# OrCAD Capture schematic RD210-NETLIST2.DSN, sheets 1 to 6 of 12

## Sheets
1 12: size Custom
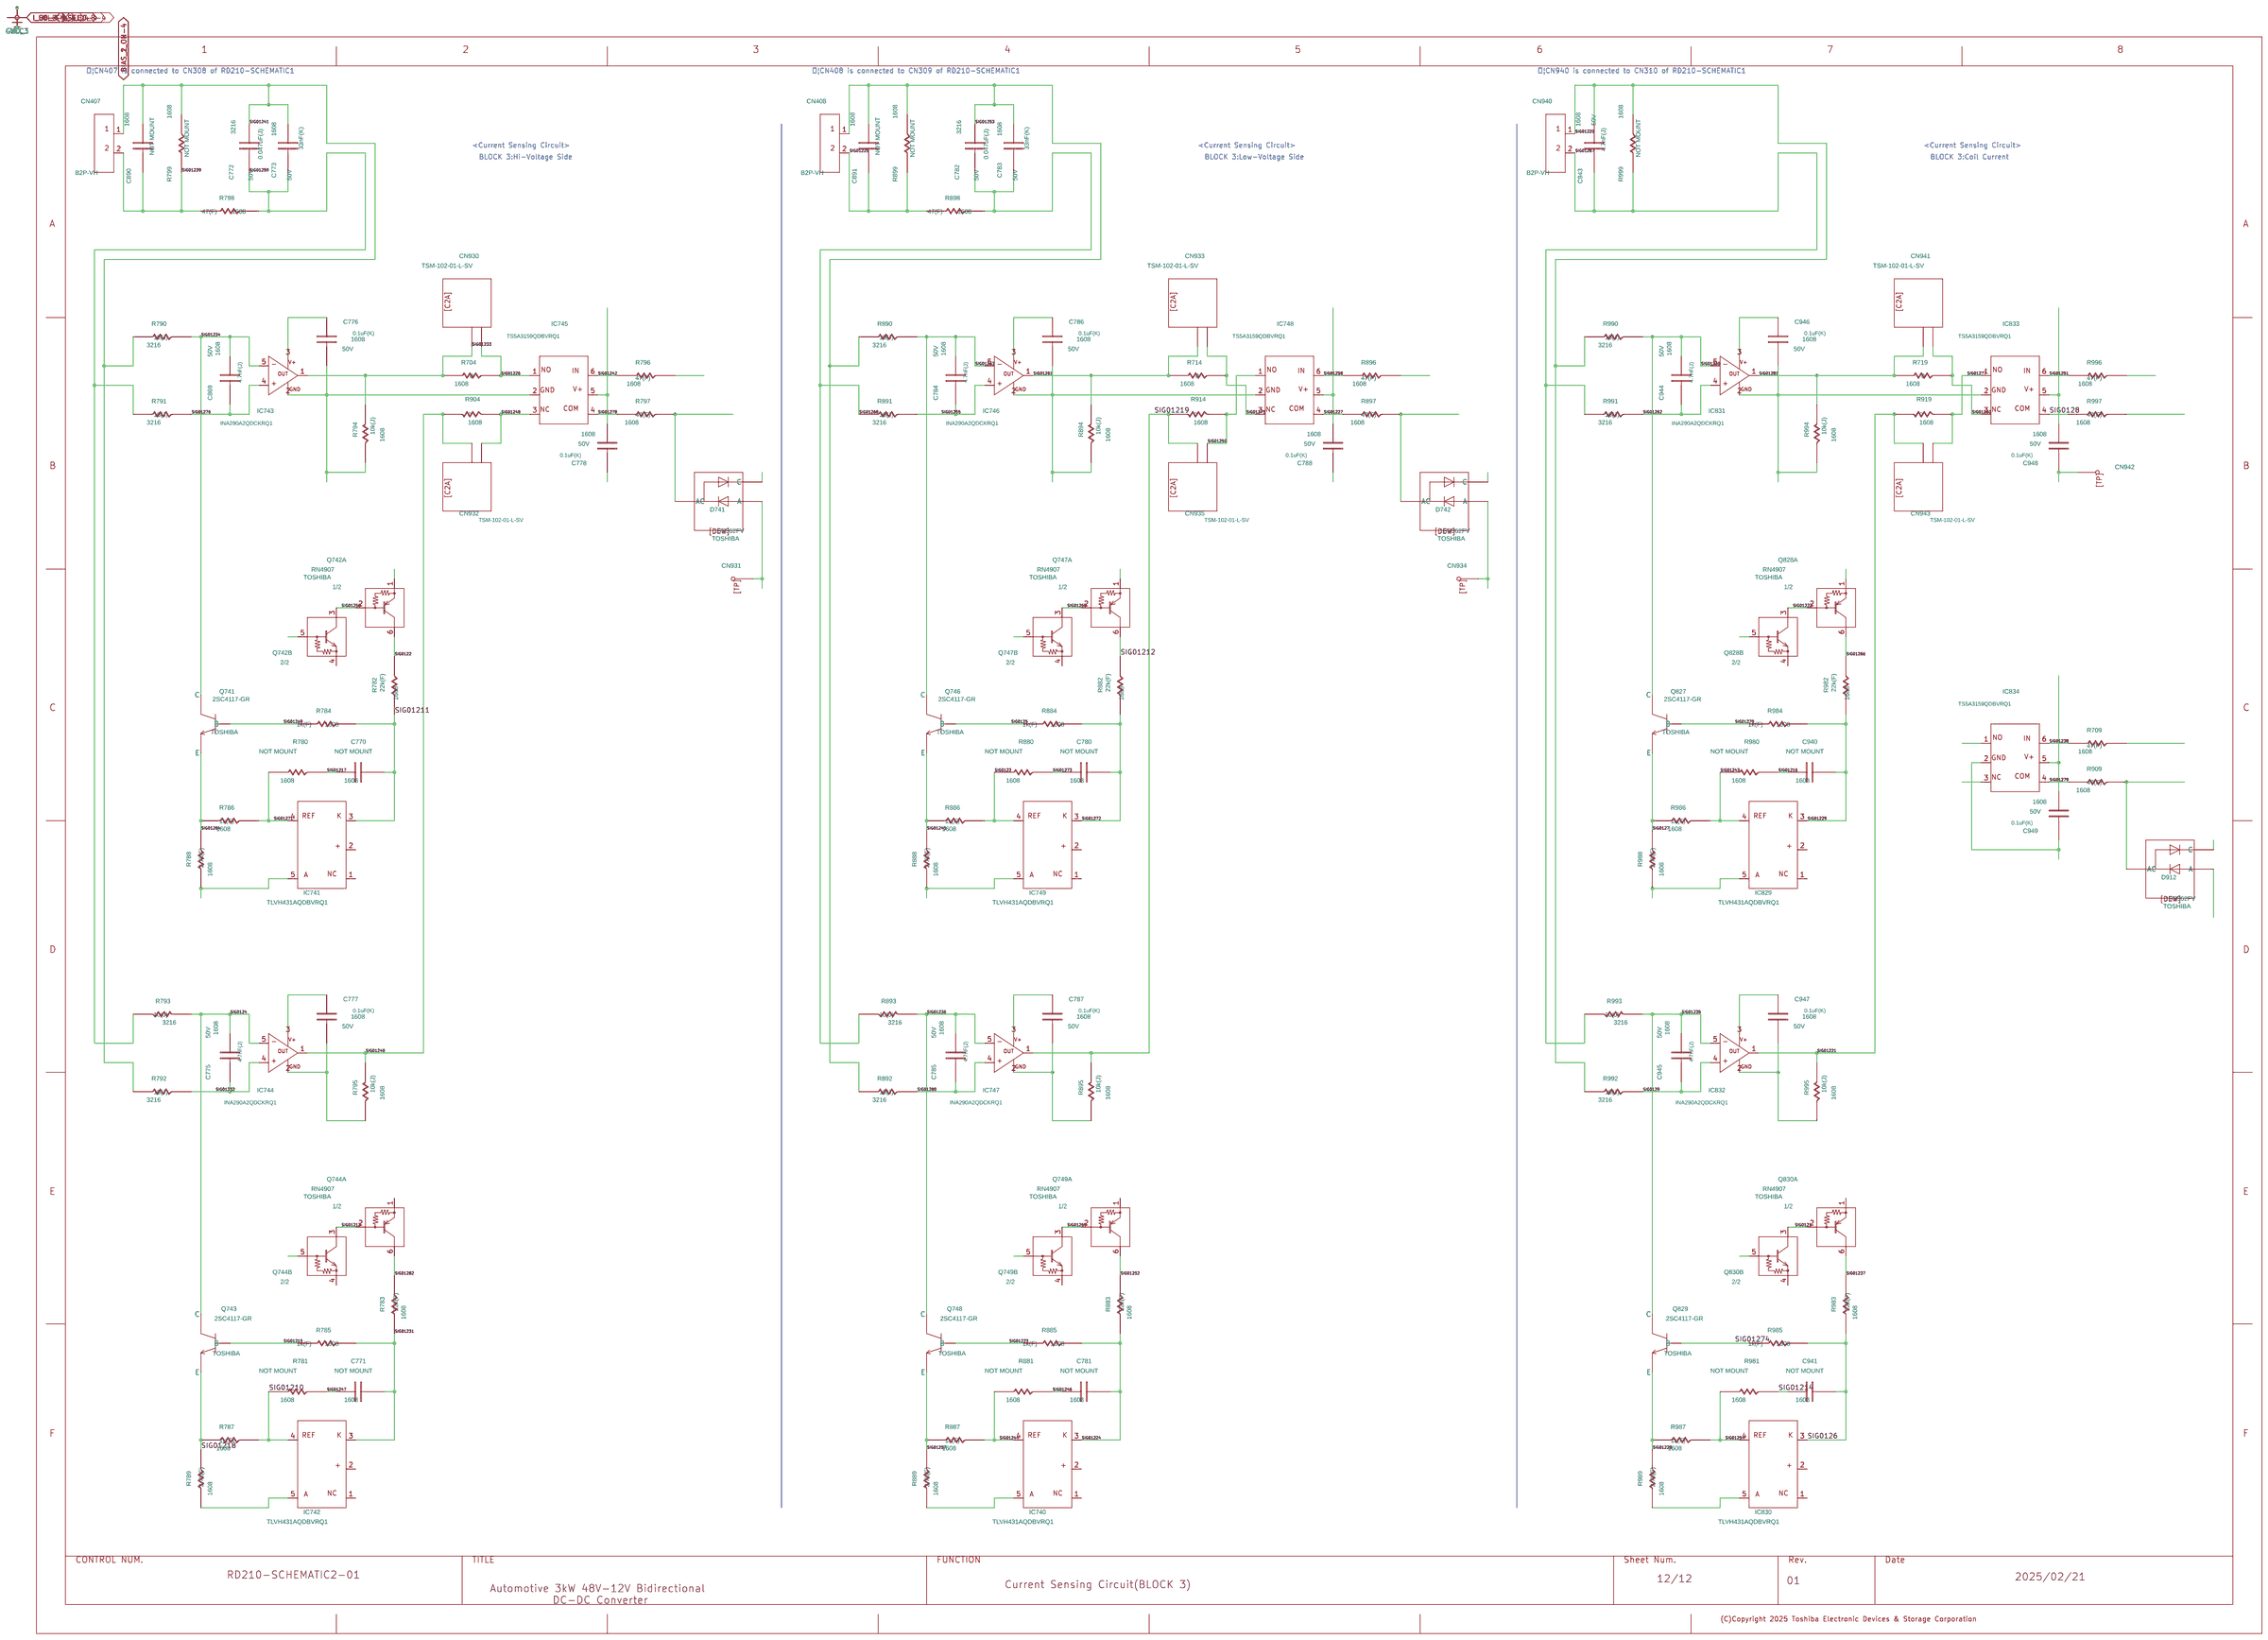
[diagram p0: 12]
2 11: size Custom
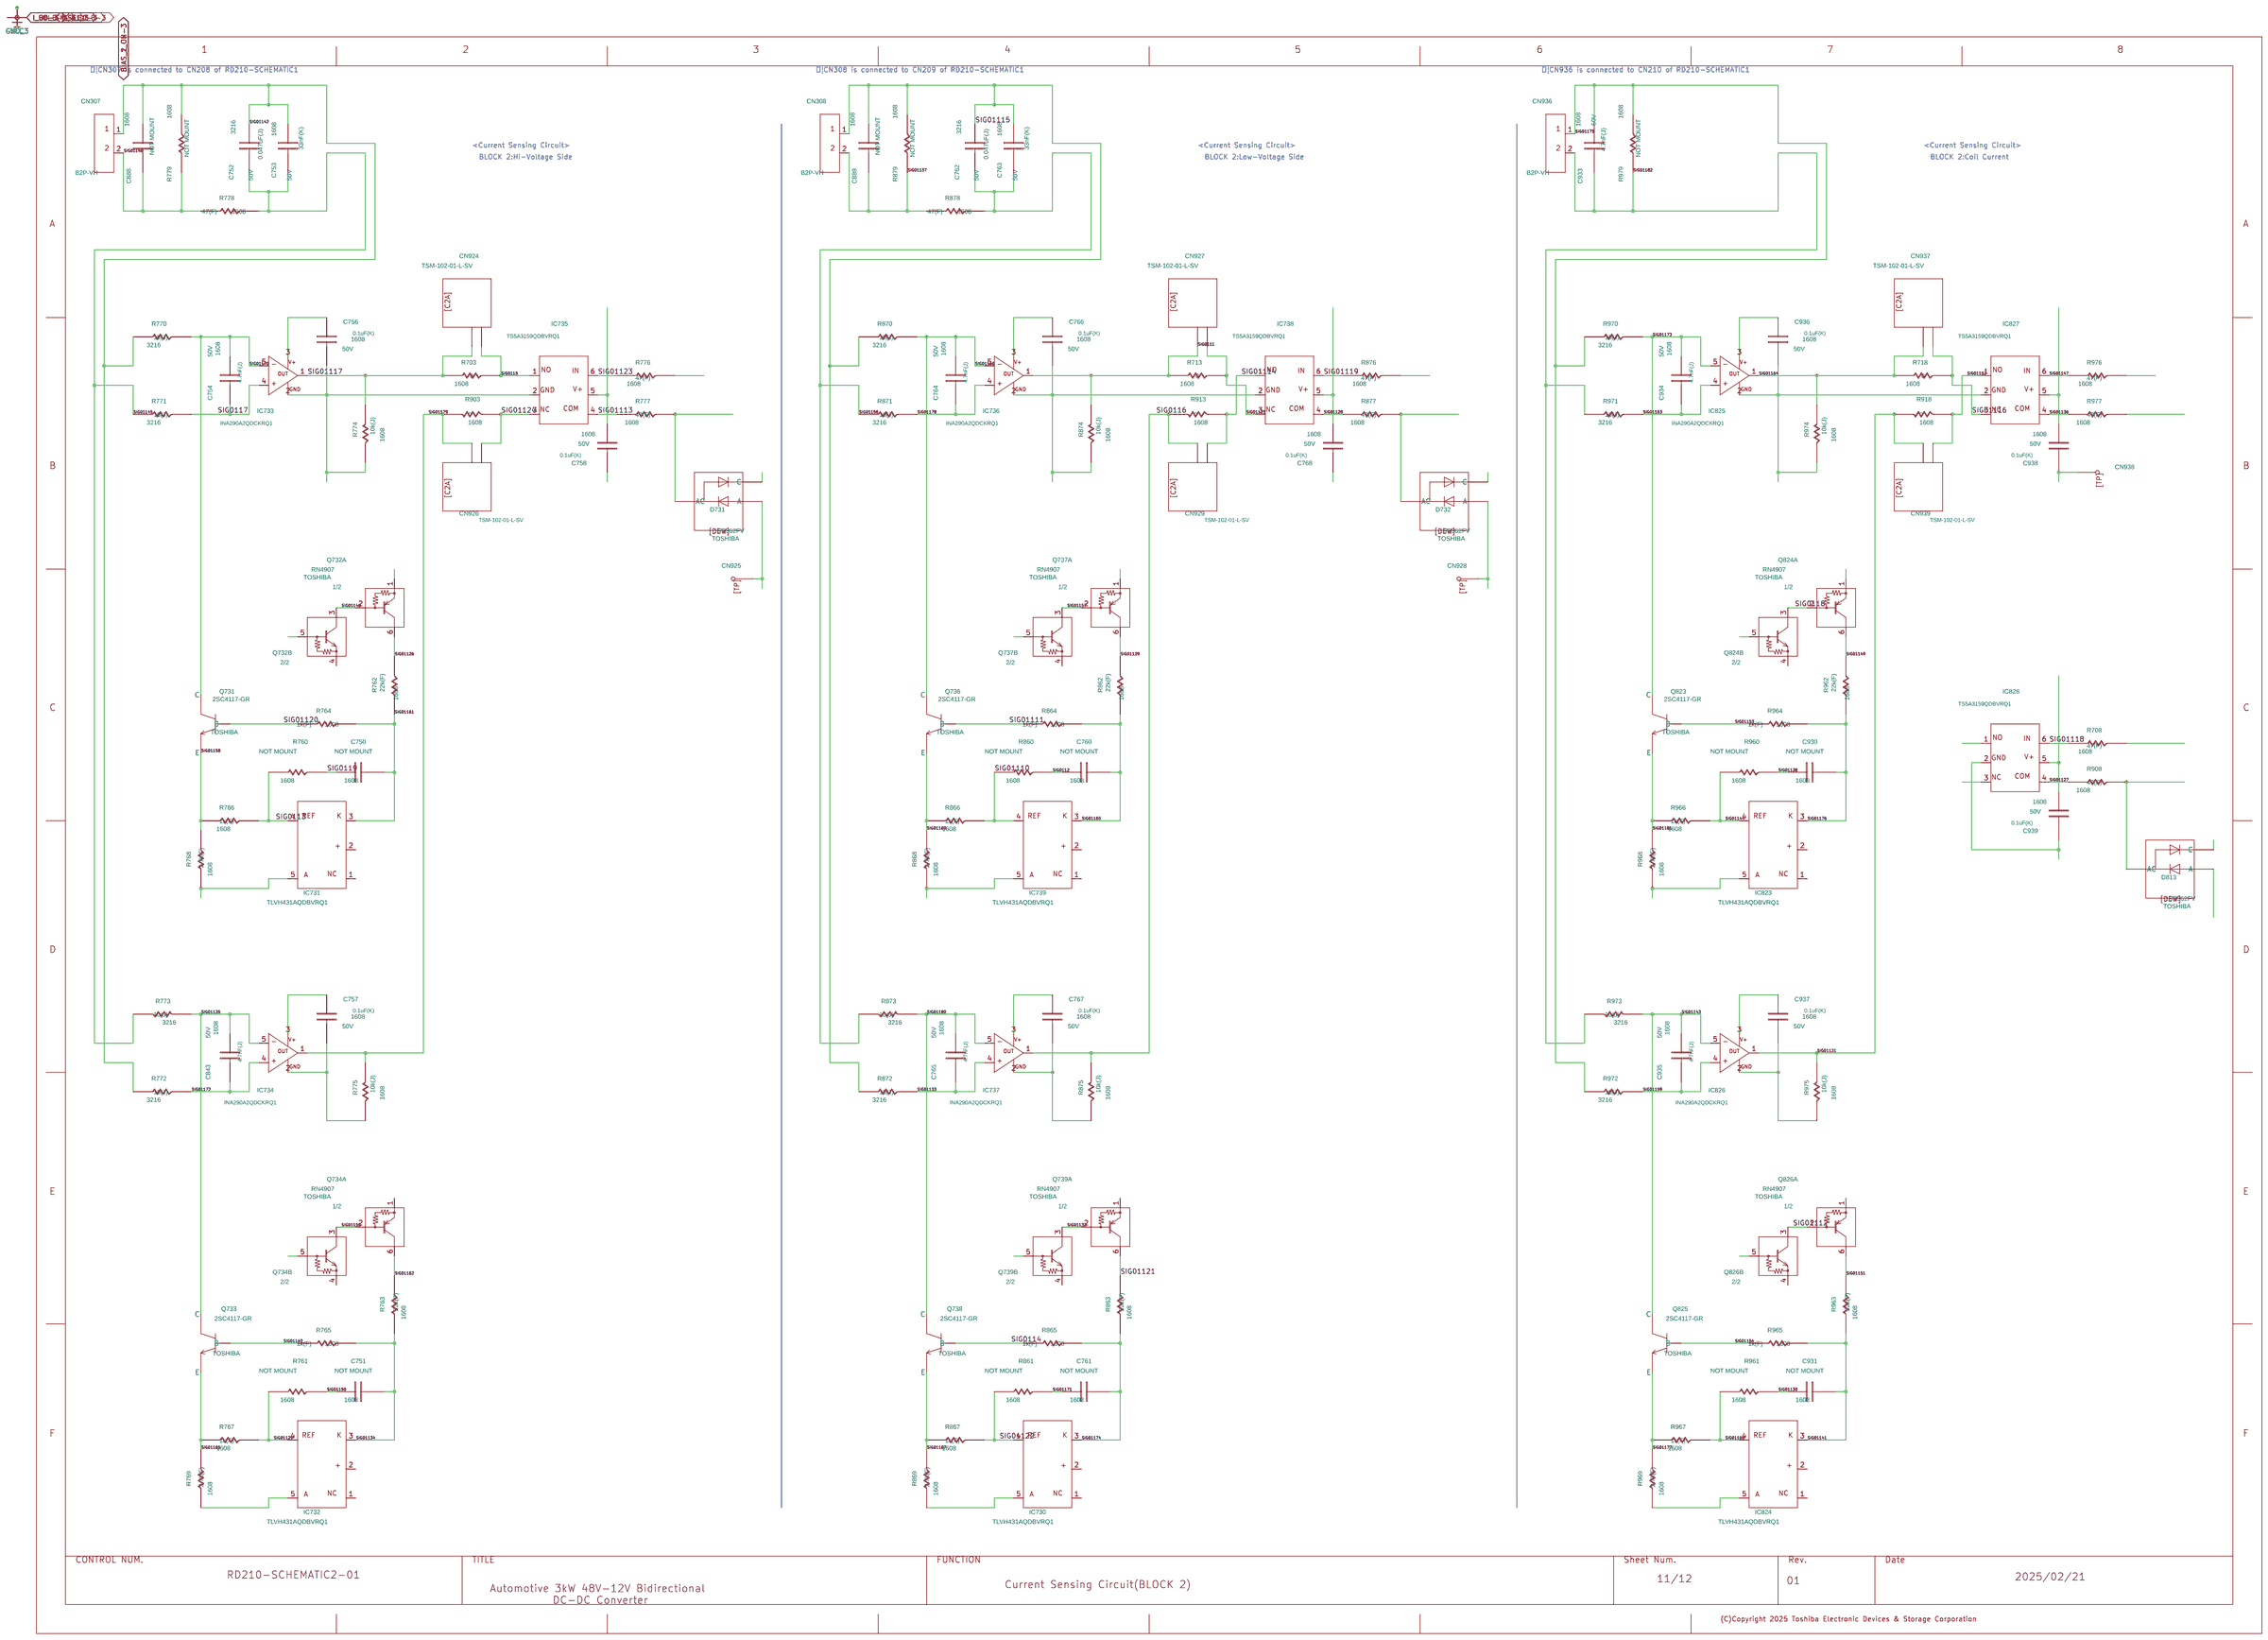
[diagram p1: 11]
3 10: size Custom
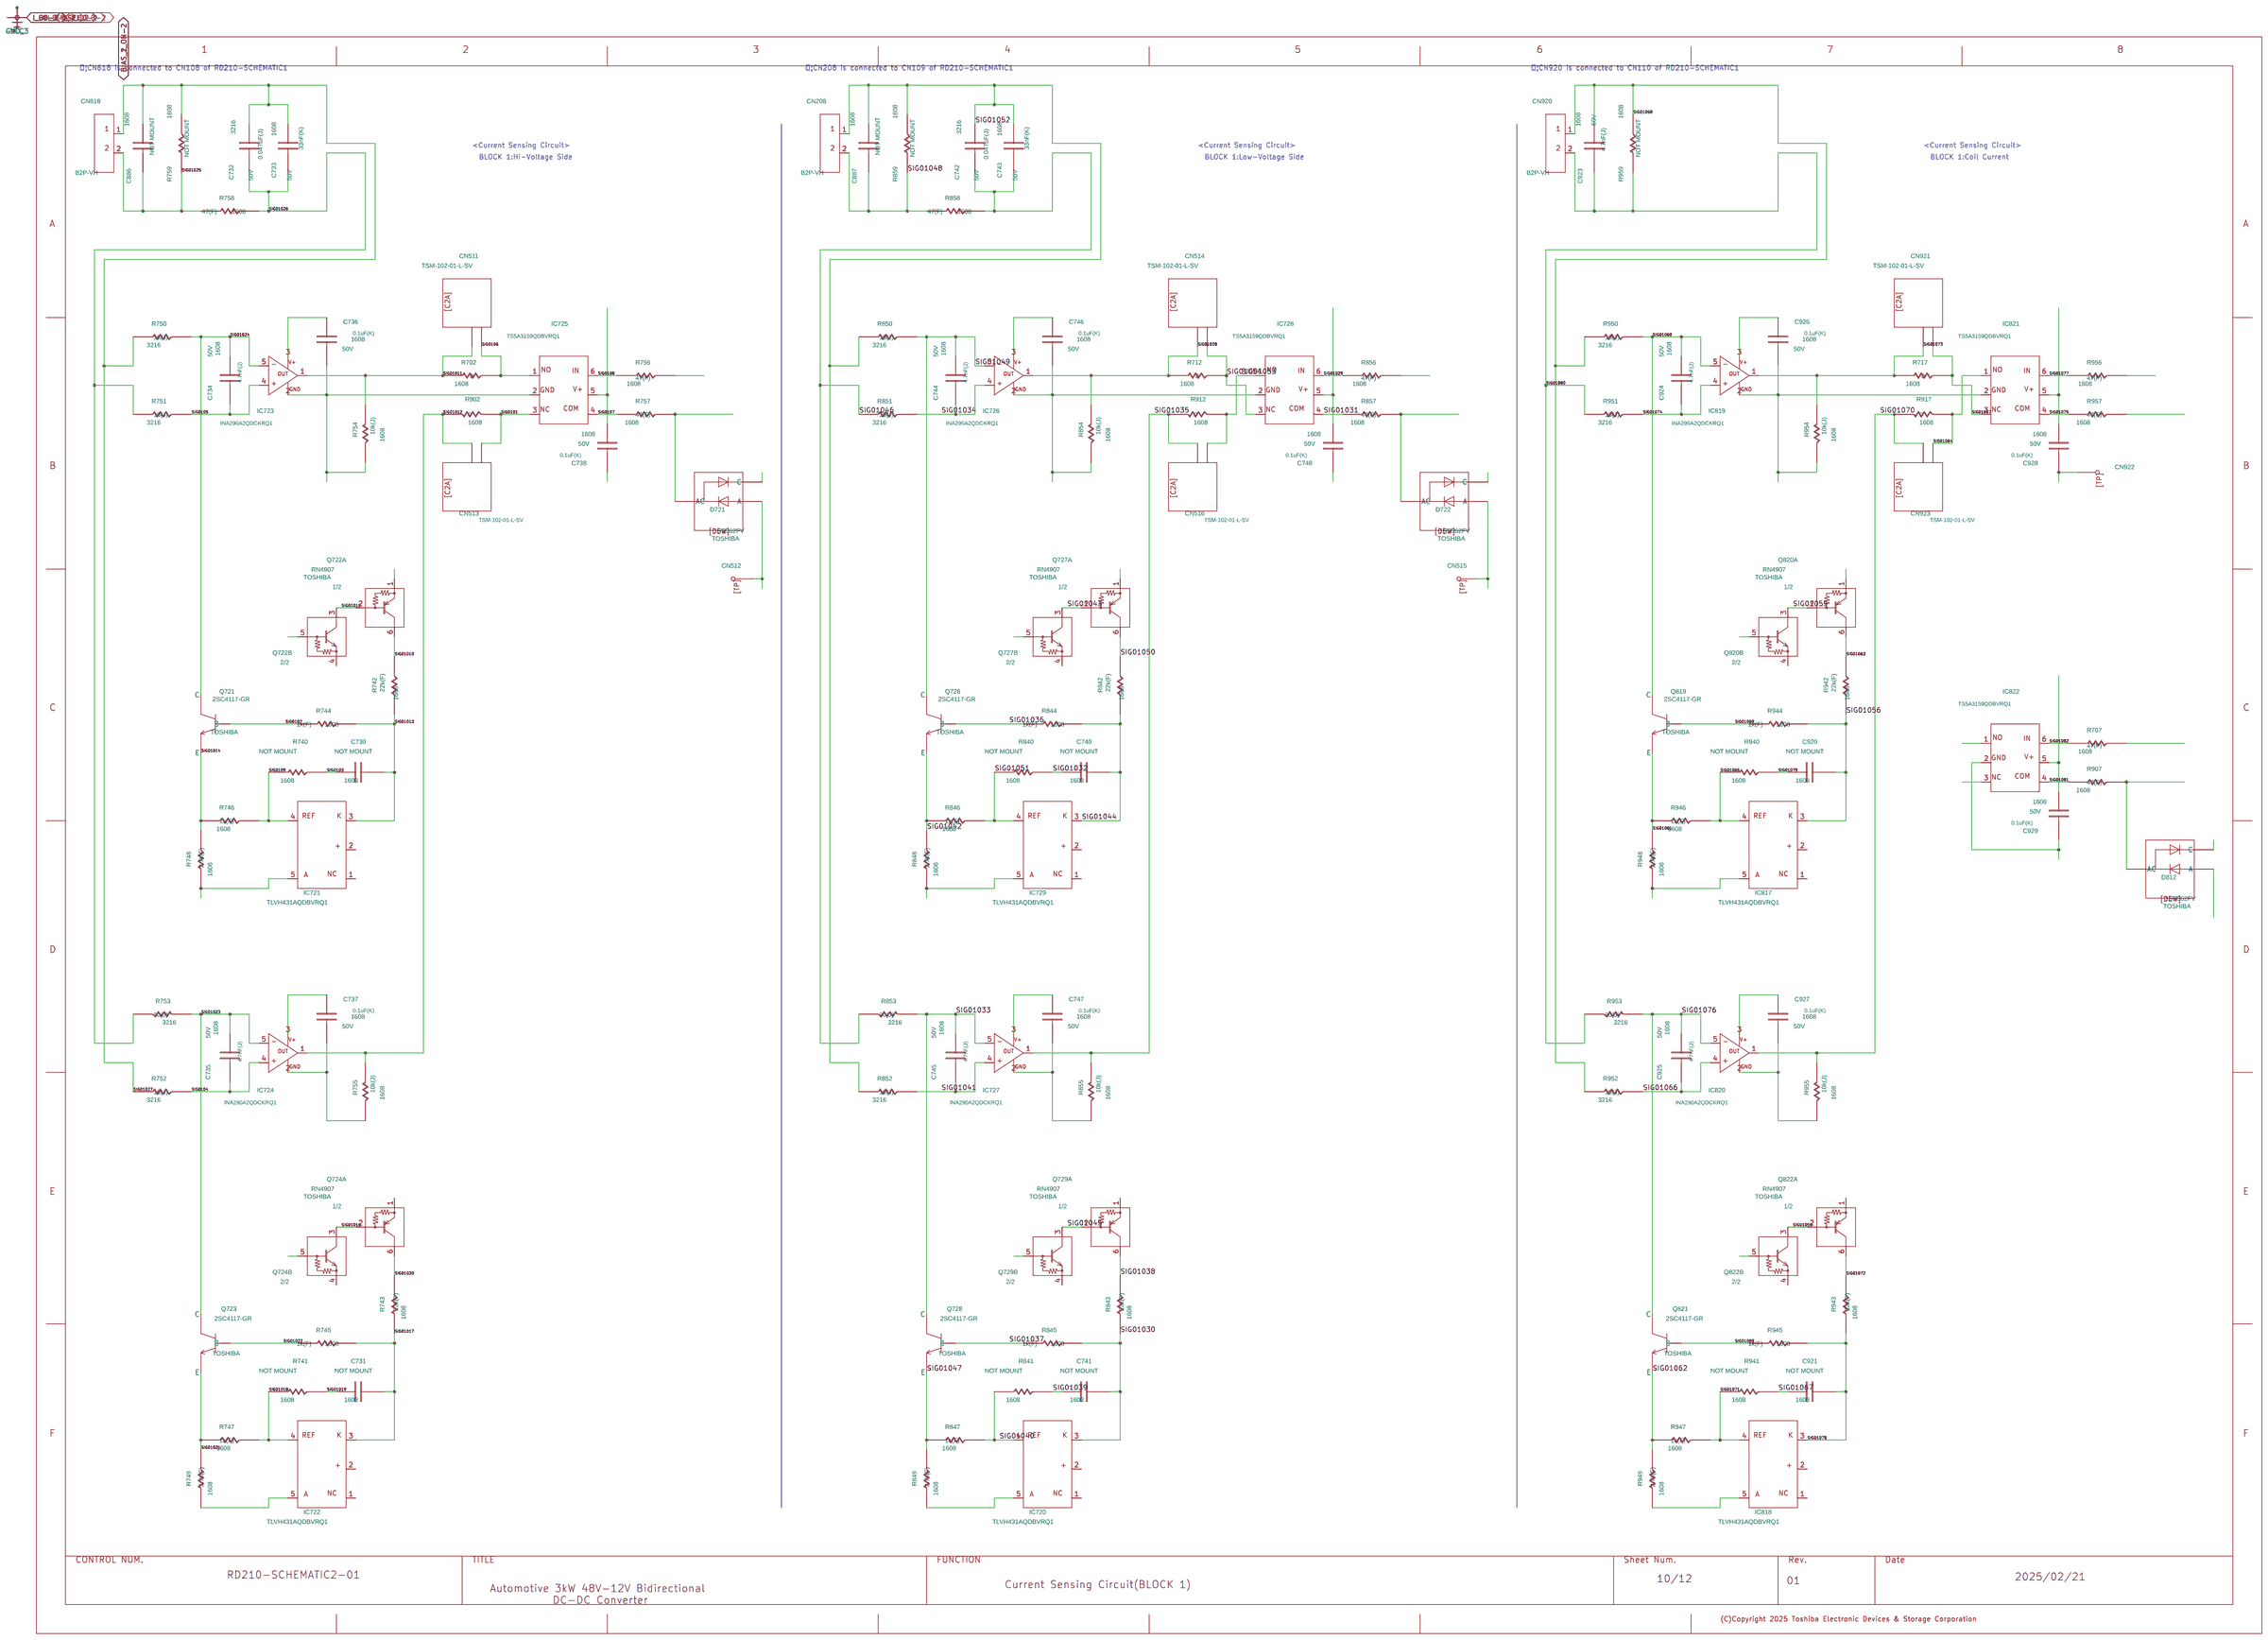
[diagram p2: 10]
4 9: size Custom
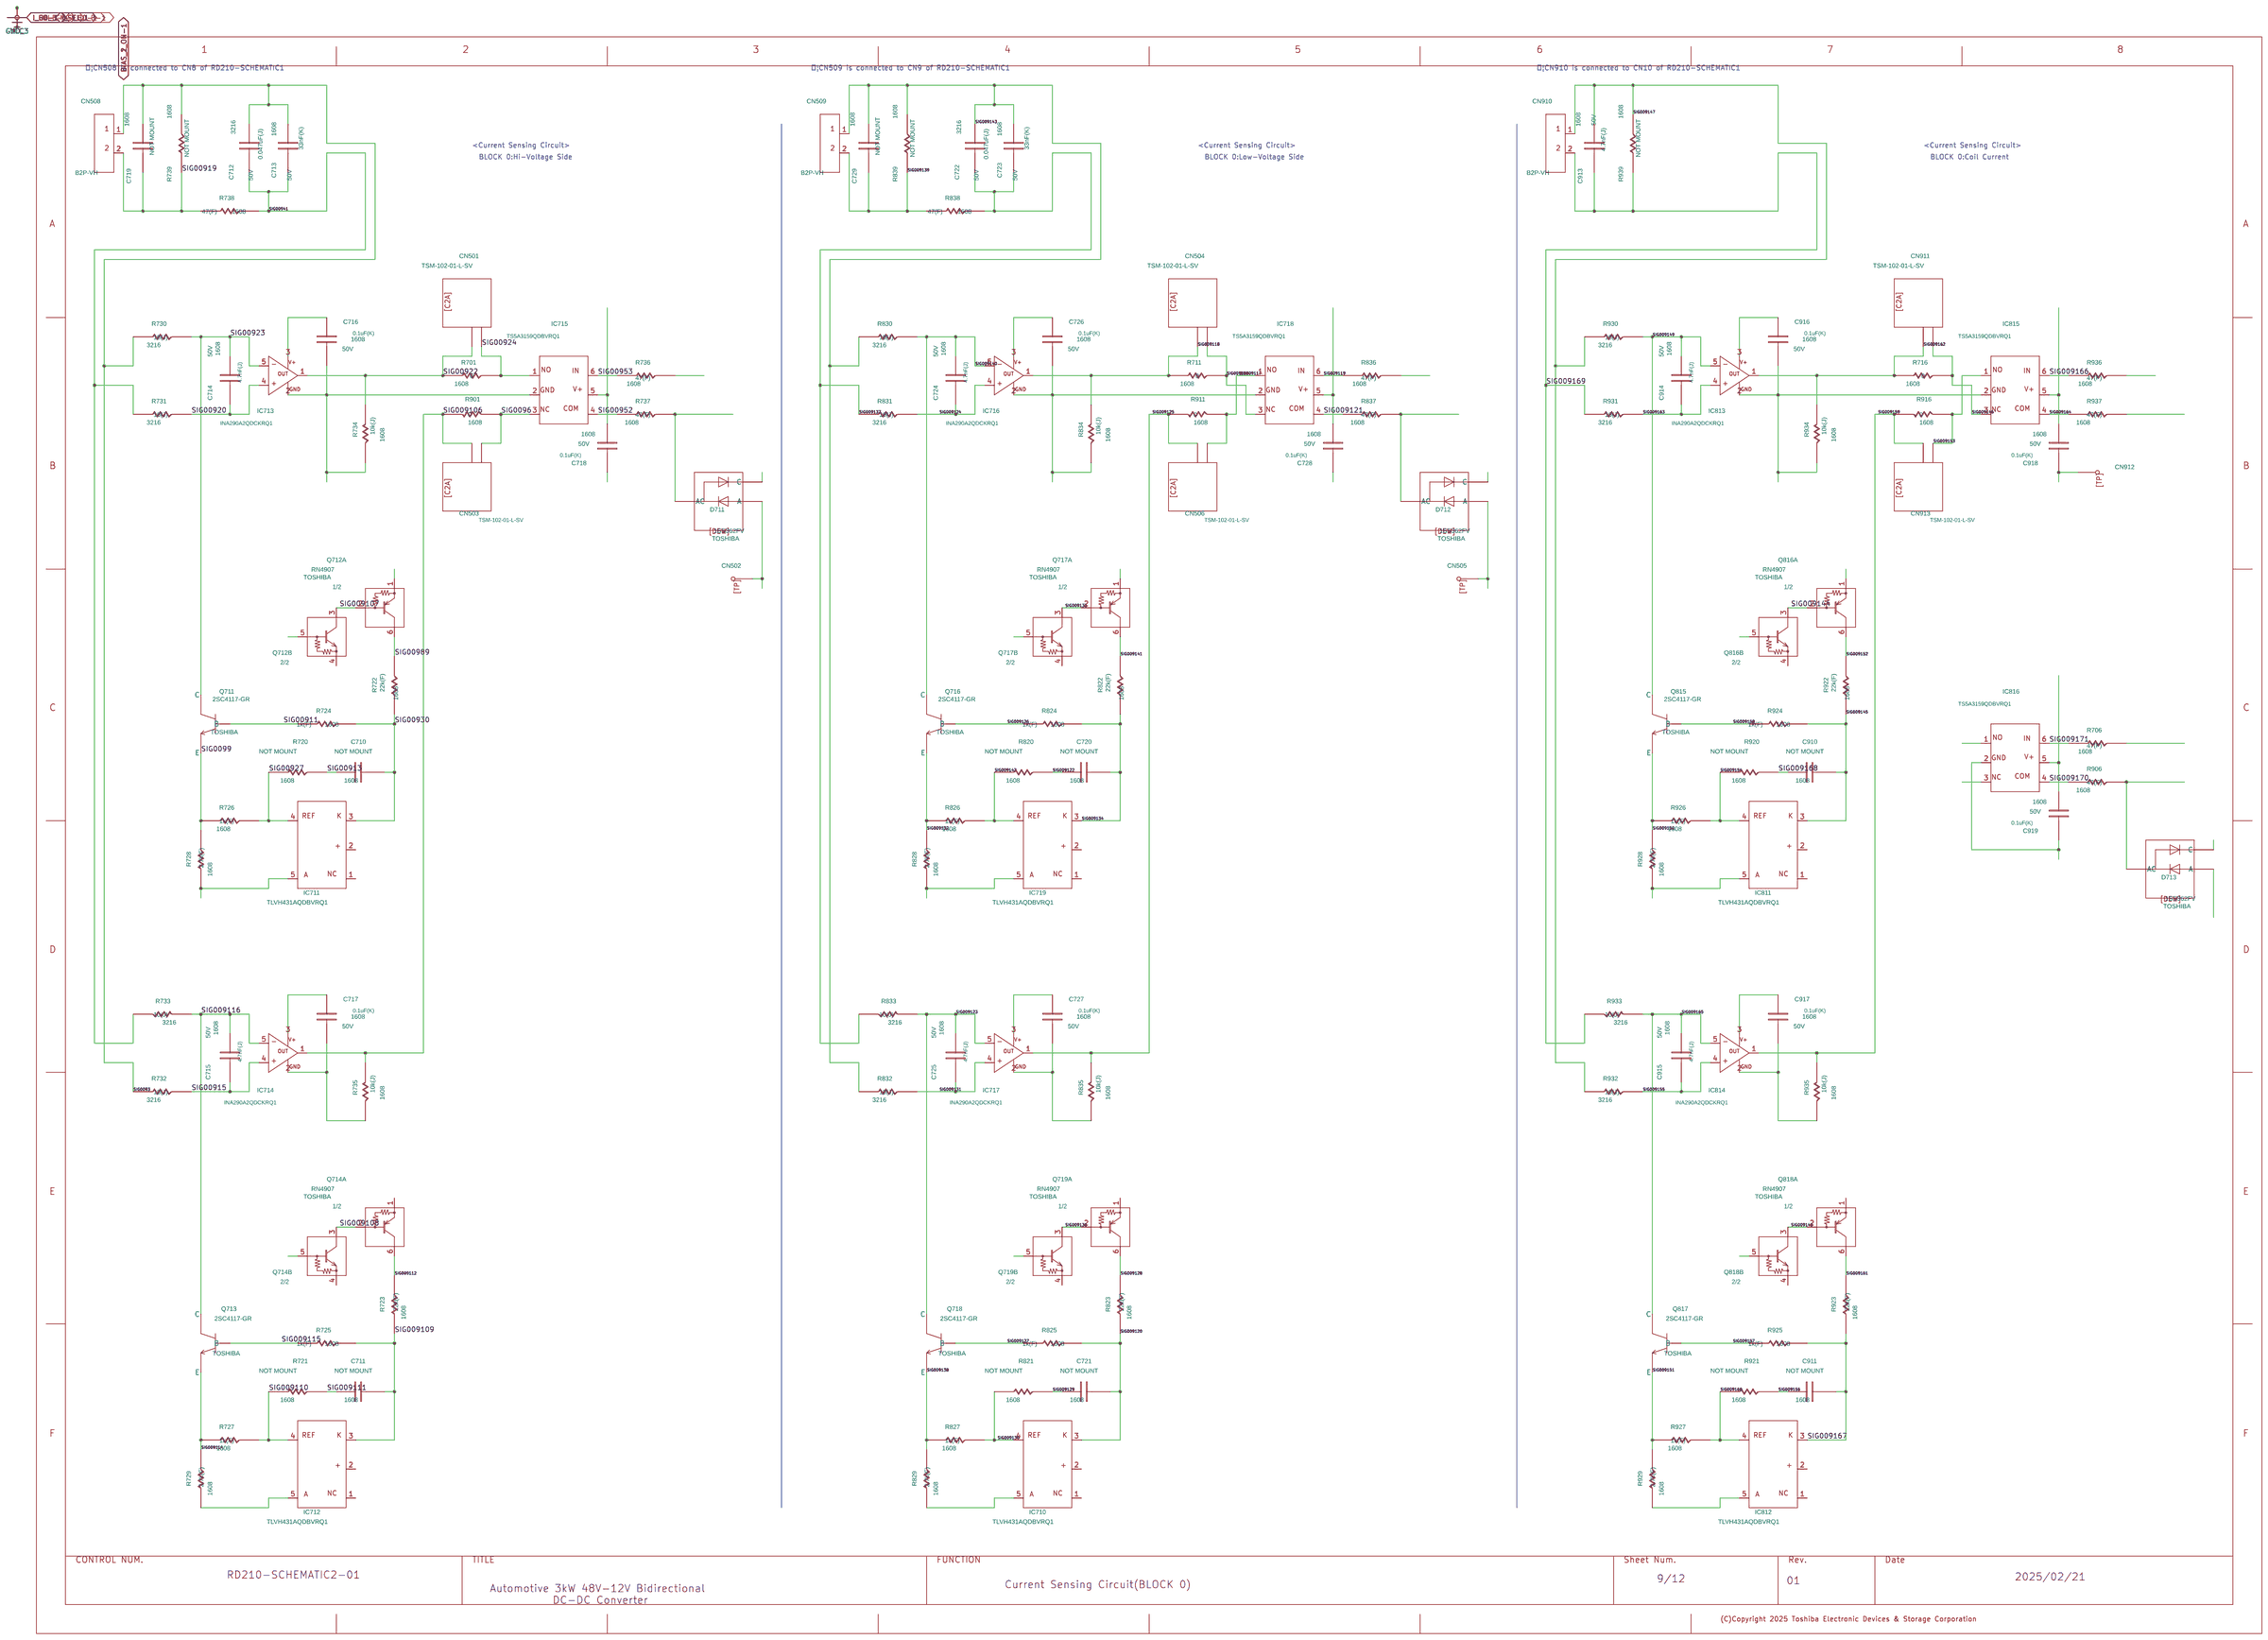
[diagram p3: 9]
5 8: size Custom
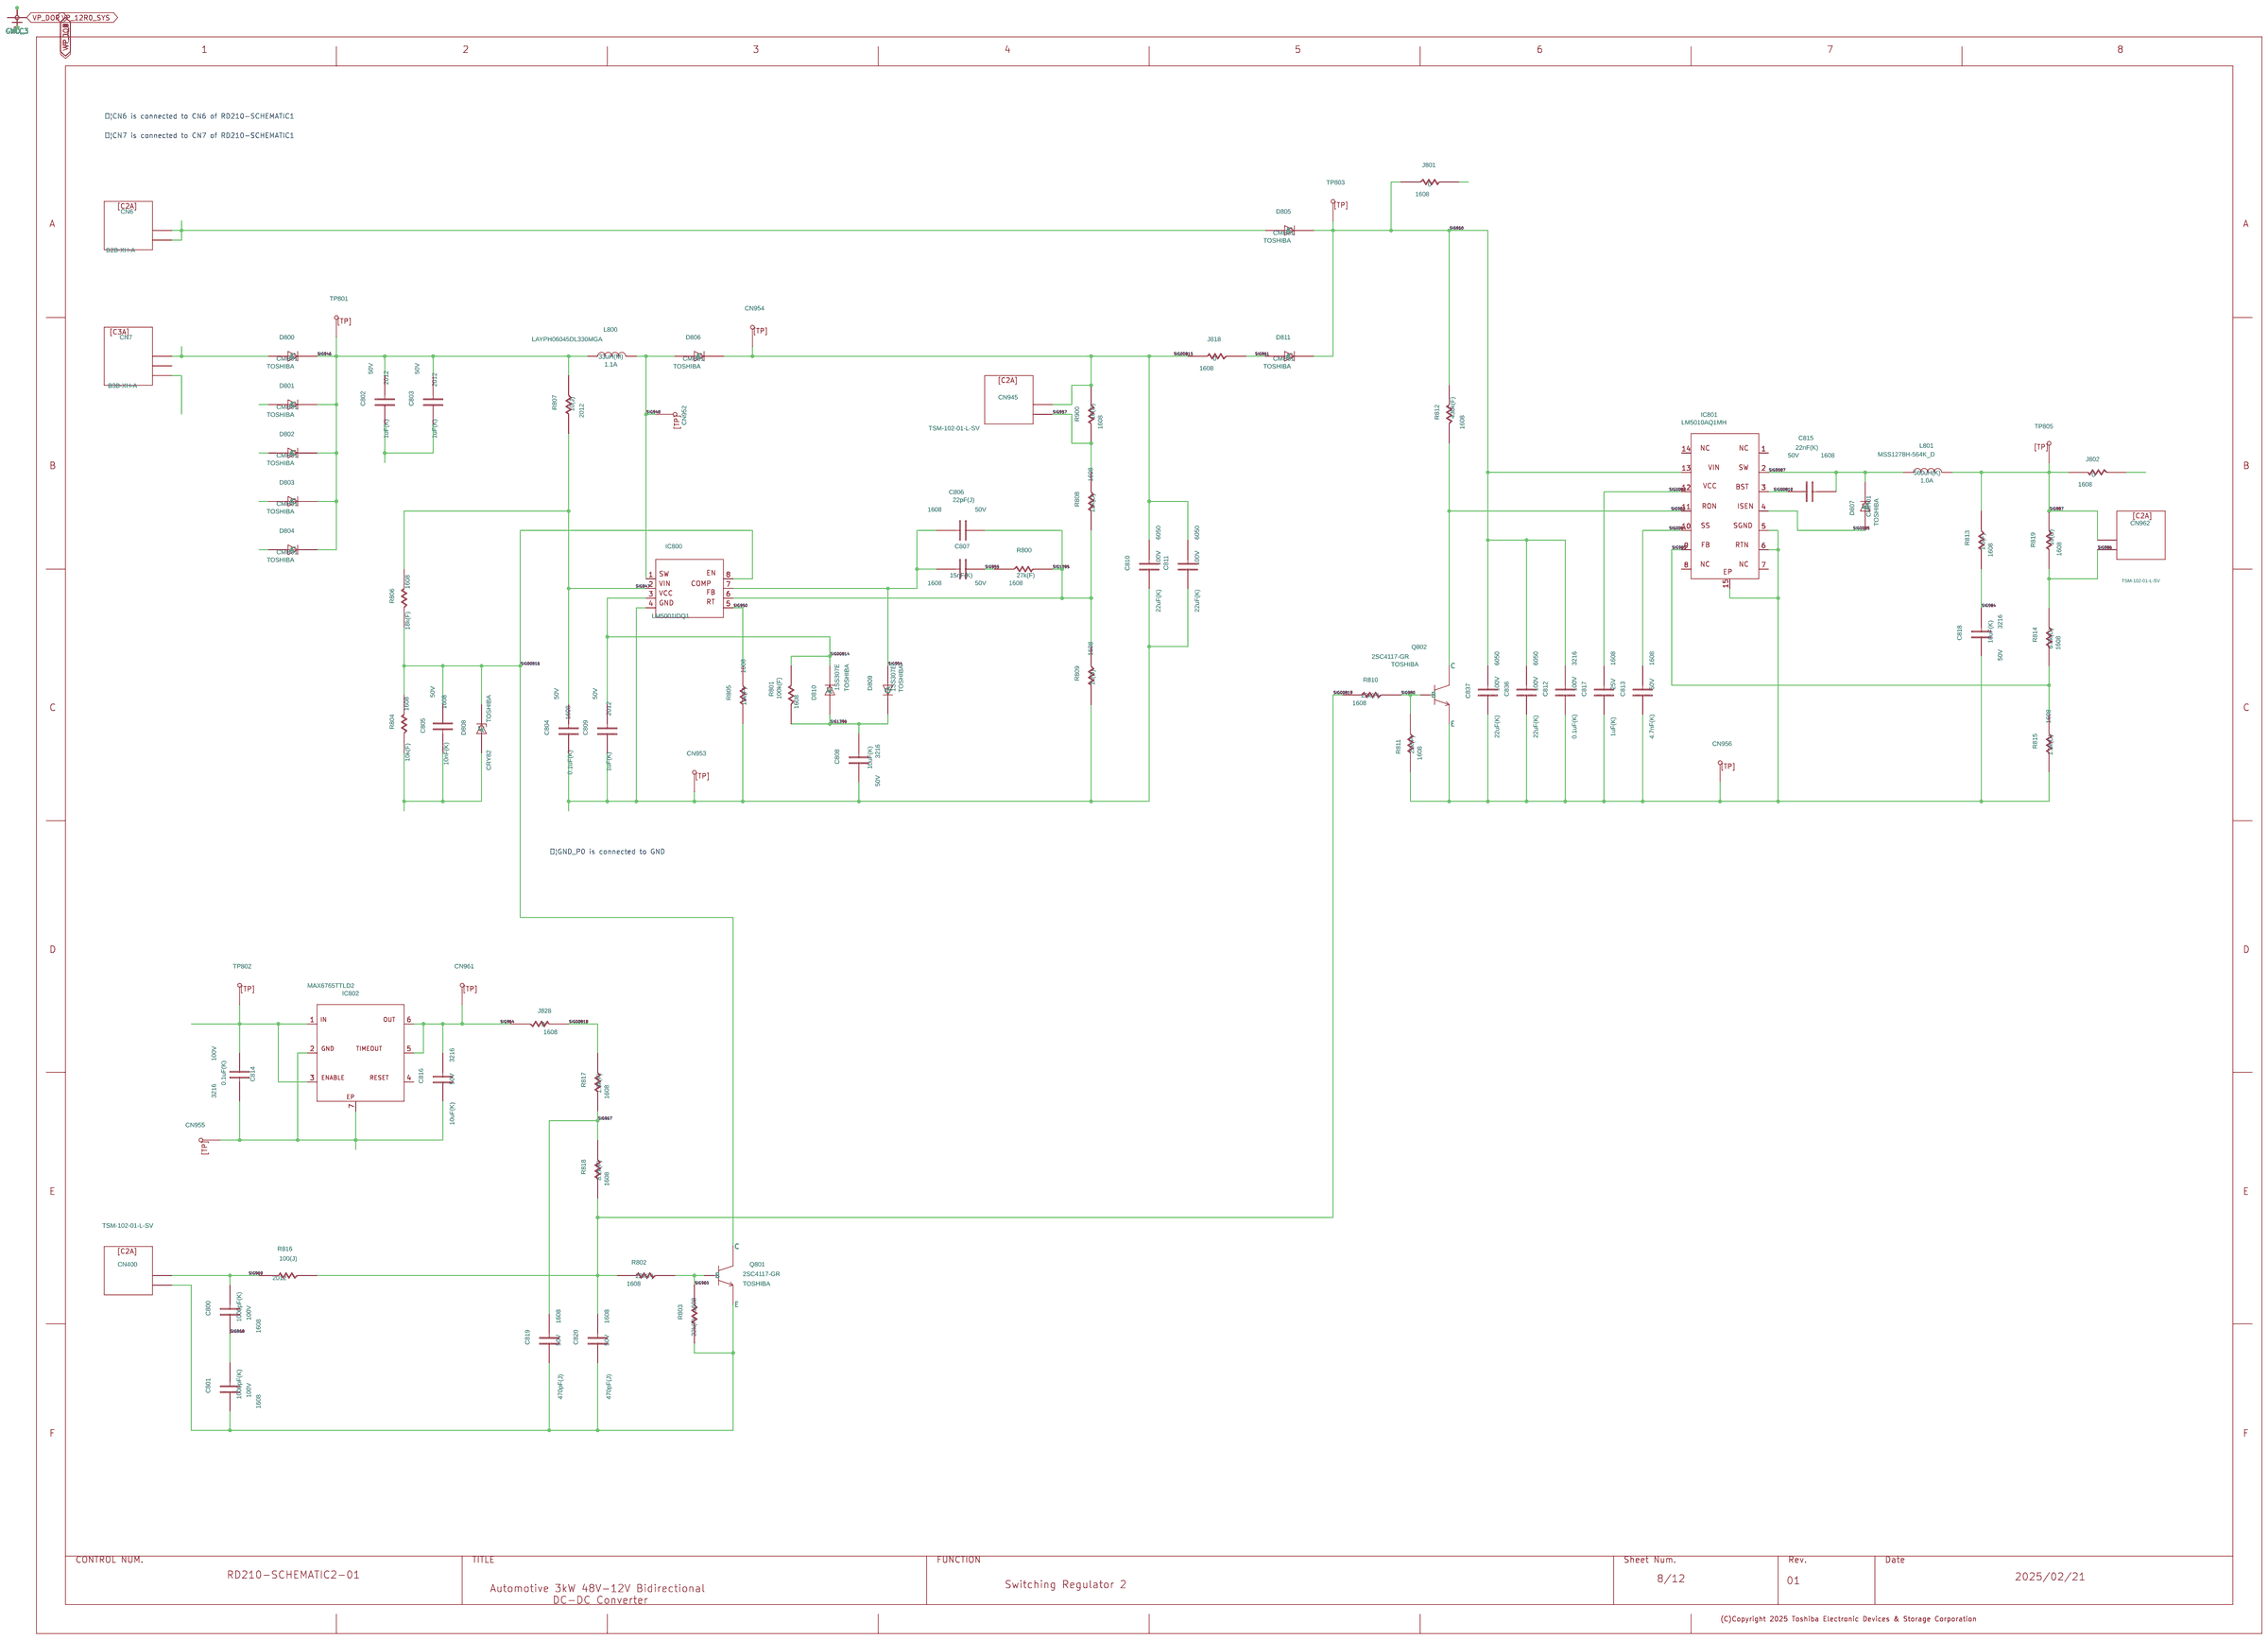
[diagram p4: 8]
6 7: size Custom
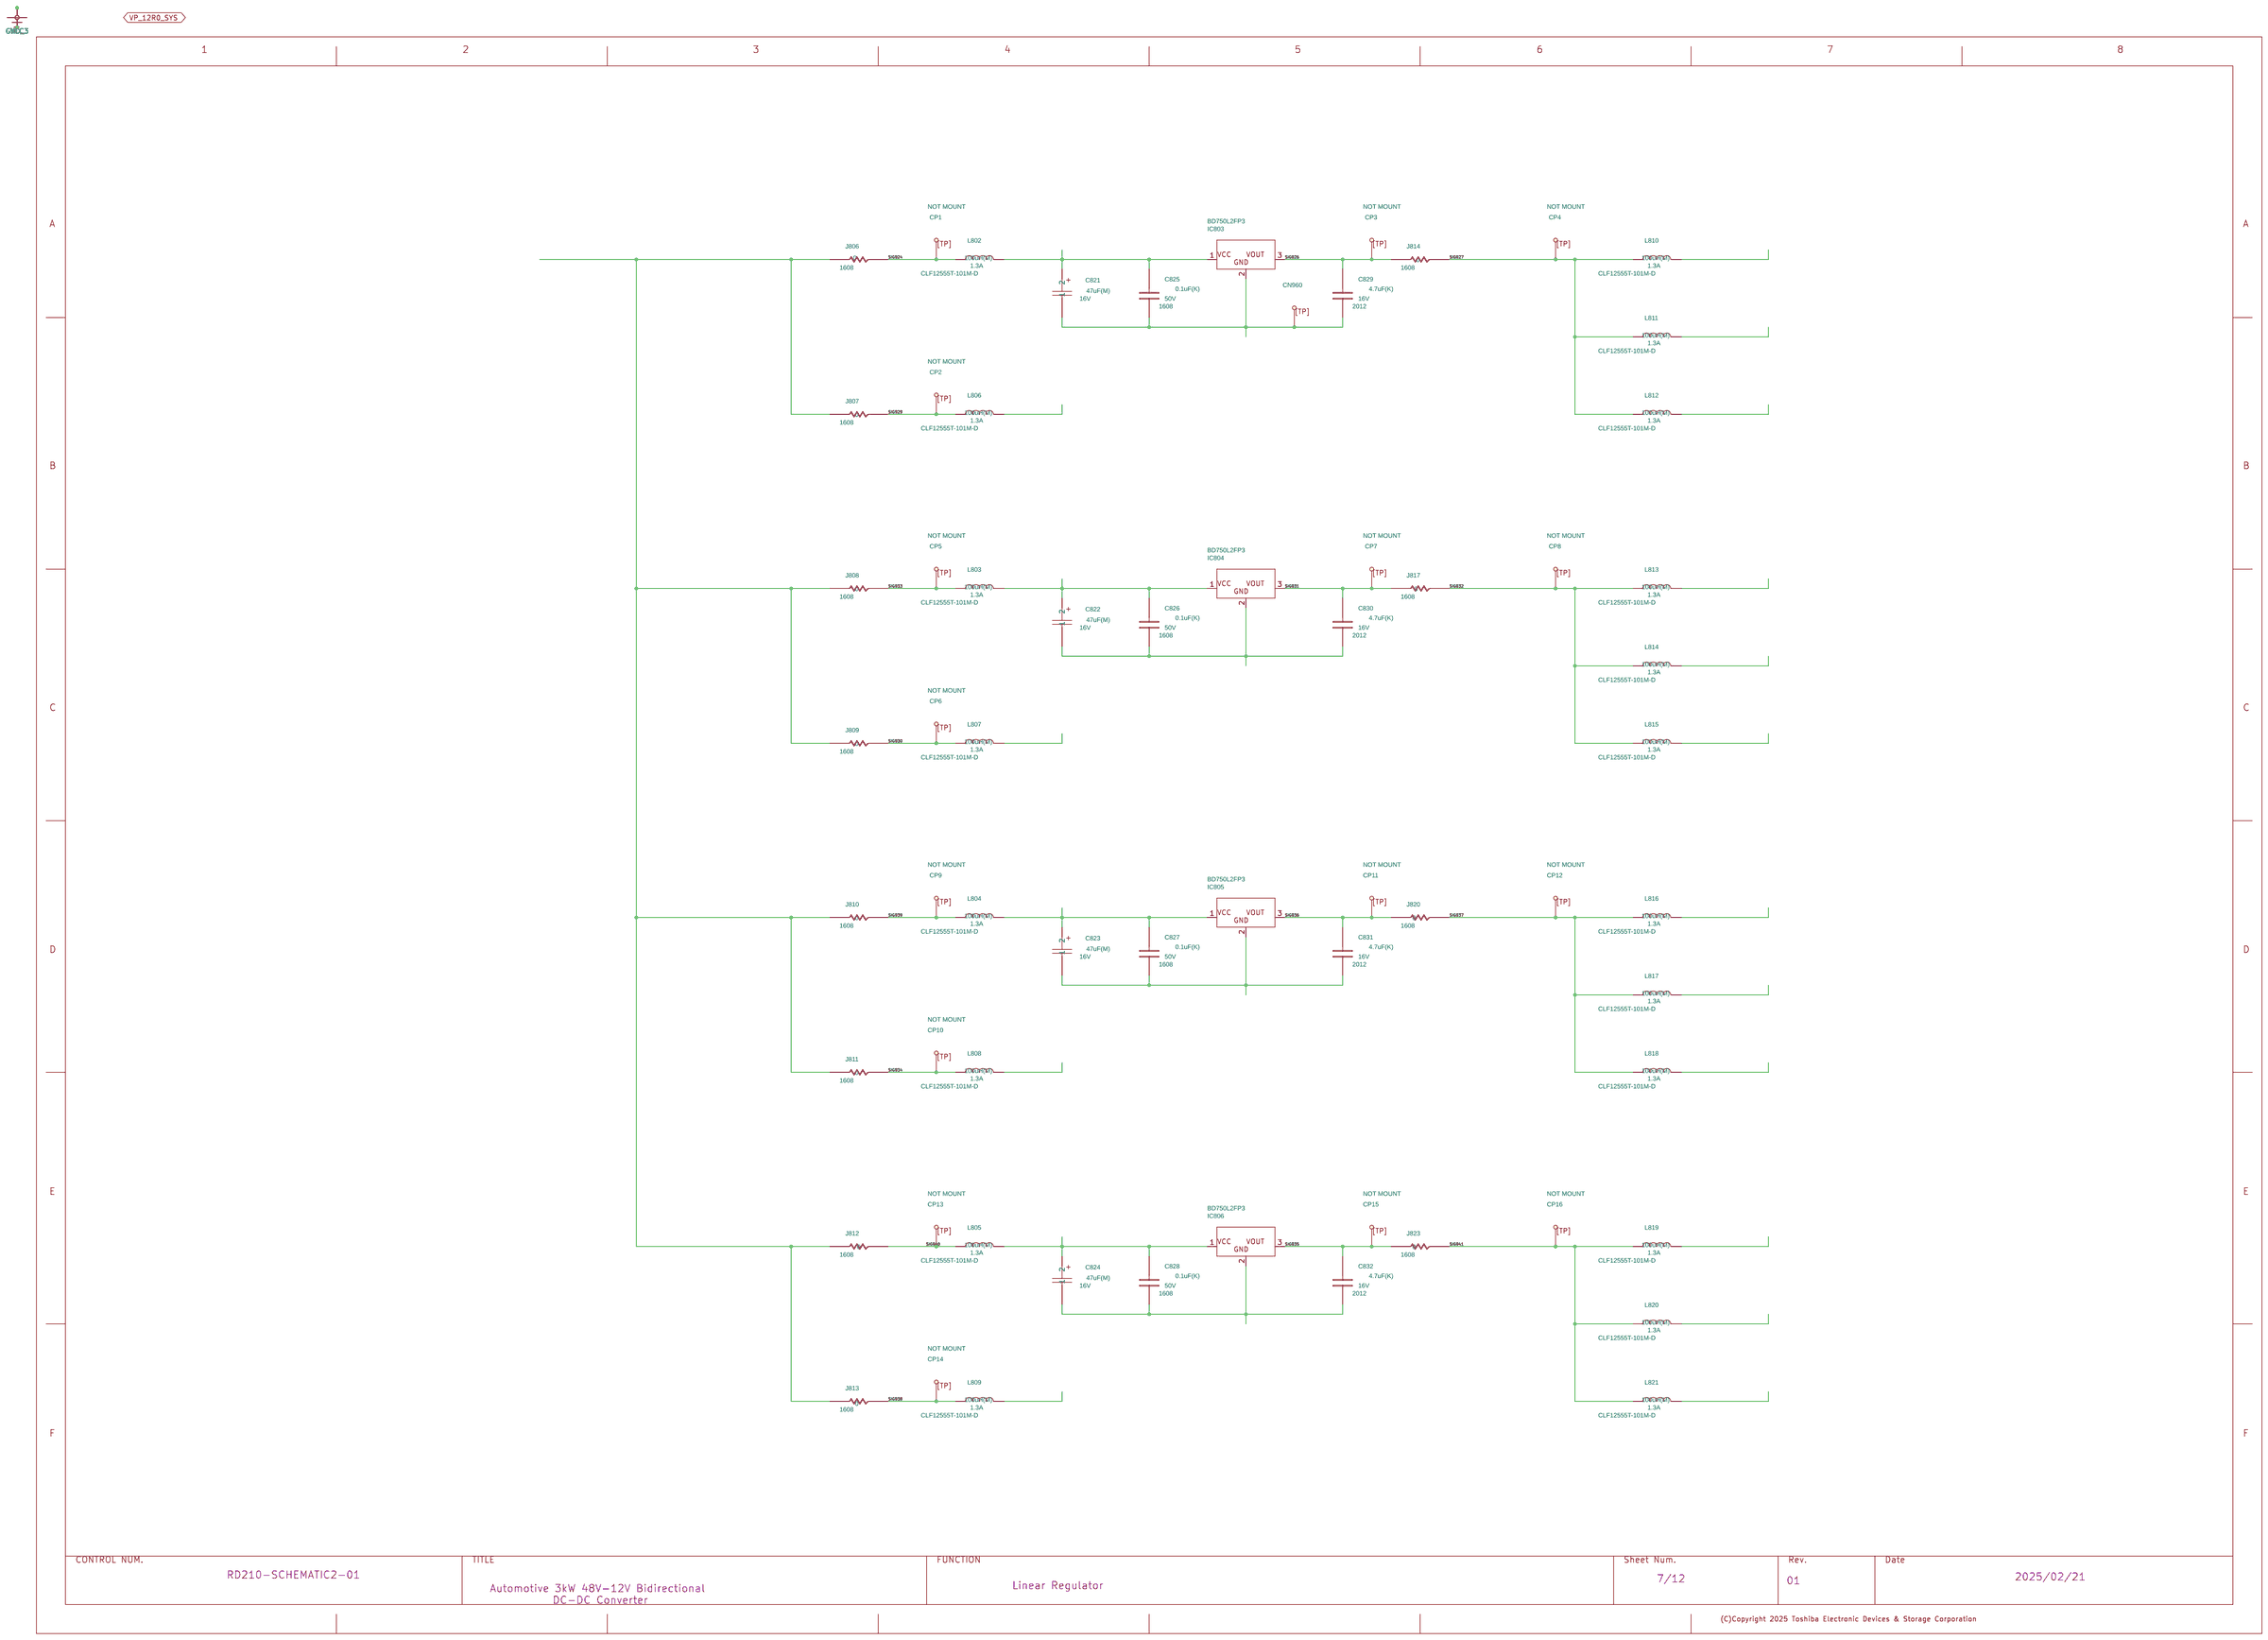
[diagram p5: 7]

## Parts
sheet 7
C821  CP
C822  CP
C823  CP
C824  CP
C825  C
C826  C
C827  C
C828  C
C829  C
C830  C
C831  C
C832  C
CN960  TP
CP1  TP
CP2  TP
CP3  TP
CP4  TP
CP5  TP
CP6  TP
CP7  TP
CP8  TP
CP9  TP
CP10  TP
CP11  TP
CP12  TP
CP13  TP
CP14  TP
CP15  TP
CP16  TP
IC803  BD750L2FP3
IC804  BD750L2FP3
IC805  BD750L2FP3
IC806  BD750L2FP3
J806  R
J807  R
J808  R
J809  R
J810  R
J811  R
J812  R
J813  R
J814  R
J817  R
J820  R
J823  R
L802  L
L803  L
L804  L
L805  L
L806  L
L807  L
L808  L
L809  L
L810  L
L811  L
L812  L
L813  L
L814  L
L815  L
L816  L
L817  L
L818  L
L819  L
L820  L
L821  L
U?#5  WAKU_DEF_A3
sheet 8
C800  C
C801  C
C802  C
C803  C
C804  C
C805  C
C806  C
C807  C
C808  C
C809  C
C810  C
C811  C
C812  C
C813  C
C814  C
C815  C
C816  C
C817  C
C818  C
C819  C
C820  C
C836  C
C837  C
CN6  C2A
CN7  C3A
CN400  C2A
CN945  C2A
CN952  TP
CN953  TP
CN954  TP
CN955  TP
CN956  TP
CN961  TP
CN962  C2A
D800  D
D801  D
D802  D
D803  D
D804  D
D805  D
D806  D
D807  D
D808  ZD
D809  D
D810  D
D811  D
IC800  LM5001IDQ1
IC801  LM5010AQ1MH
IC802  MAX6765TTLD2
J801  R
J802  R
J818  R
J828  R
L800  L
L801  L
Q801  TRN
Q802  TRN
R800  R
R801  R
R802  R
R803  R
R804  R
R805  R
R806  R
R807  R
R808  R
R809  R
R810  R
R811  R
R812  R
R813  R
R814  R
R815  R
R816  R
R817  R
R818  R
R819  R
R900  R
TP801  TP
TP802  TP
TP803  TP
TP805  TP
U?#4  WAKU_DEF_A3
sheet 9
C710  C
C711  C
C712  C
C713  C
C714  C
C715  C
C716  C
C717  C
C718  C
C719  C
C720  C
C721  C
C722  C
C723  C
C724  C
C725  C
C726  C
C727  C
C728  C
C729  C
C910  C
C911  C
C913  C
C914  C
C915  C
C916  C
C917  C
C918  C
C919  C
CN501  C2A
CN502  TP
CN503  C2A
CN504  C2A
CN505  TP
CN506  C2A
CN508  B2P-VH
CN509  B2P-VH
CN910  B2P-VH
CN911  C2A
CN912  TP
CN913  C2A
D711  DEW
D712  DEW
D713  DEW
IC710  TLVH431AQDBVRQ1
IC711  TLVH431AQDBVRQ1
IC712  TLVH431AQDBVRQ1
IC713  INA290A2QDCKRQ1
IC714  INA290A2QDCKRQ1
IC715  TS5A3159QDBVRQ1
IC716  INA290A2QDCKRQ1
IC717  INA290A2QDCKRQ1
IC718  TS5A3159QDBVRQ1
IC719  TLVH431AQDBVRQ1
IC811  TLVH431AQDBVRQ1
IC812  TLVH431AQDBVRQ1
IC813  INA290A2QDCKRQ1
IC814  INA290A2QDCKRQ1
IC815  TS5A3159QDBVRQ1
IC816  TS5A3159QDBVRQ1
Q711  TRN
Q712  RN4907_Q2  (sections A,B)
Q713  TRN
Q714  RN4907_Q2  (sections A,B)
Q716  TRN
Q717  RN4907_Q2  (sections A,B)
Q718  TRN
Q719  RN4907_Q2  (sections A,B)
Q815  TRN
Q816  RN4907_Q2  (sections A,B)
Q817  TRN
Q818  RN4907_Q2  (sections A,B)
R701  R
R706  R
R711  R
R716  R
R720  R
R721  R
R722  R
R723  R
R724  R
R725  R
R726  R
R727  R
R728  R
R729  R
R730  R
R731  R
R732  R
R733  R
R734  R
R735  R
R736  R
R737  R
R738  R
R739  R
R820  R
R821  R
R822  R
R823  R
R824  R
R825  R
R826  R
R827  R
R828  R
R829  R
R830  R
R831  R
R832  R
R833  R
R834  R
R835  R
R836  R
R837  R
R838  R
R839  R
R901  R
R906  R
R911  R
R916  R
R920  R
R921  R
R922  R
R923  R
R924  R
R925  R
R926  R
R927  R
R928  R
R929  R
R930  R
R931  R
R932  R
R933  R
R934  R
R935  R
R936  R
R937  R
R939  R
U?#3  WAKU_DEF_A3
sheet 10
C730  C
C731  C
C732  C
C733  C
C734  C
C735  C
C736  C
C737  C
C738  C
C740  C
C741  C
C742  C
C743  C
C744  C
C745  C
C746  C
C747  C
C748  C
C886  C
C887  C
C920  C
C921  C
C923  C
C924  C
C925  C
C926  C
C927  C
C928  C
C929  C
CN208  B2P-VH
CN511  C2A
CN512  TP
CN513  C2A
CN514  C2A
CN515  TP
CN516  C2A
CN618  B2P-VH
CN920  B2P-VH
CN921  C2A
CN922  TP
CN923  C2A
D721  DEW
D722  DEW
D812  DEW
IC720  TLVH431AQDBVRQ1
IC721  TLVH431AQDBVRQ1
IC722  TLVH431AQDBVRQ1
IC723  INA290A2QDCKRQ1
IC724  INA290A2QDCKRQ1
IC725  TS5A3159QDBVRQ1
IC726  INA290A2QDCKRQ1
IC727  INA290A2QDCKRQ1
IC728  TS5A3159QDBVRQ1
IC729  TLVH431AQDBVRQ1
IC817  TLVH431AQDBVRQ1
IC818  TLVH431AQDBVRQ1
IC819  INA290A2QDCKRQ1
IC820  INA290A2QDCKRQ1
IC821  TS5A3159QDBVRQ1
IC822  TS5A3159QDBVRQ1
Q721  TRN
Q722  RN4907_Q2  (sections A,B)
Q723  TRN
Q724  RN4907_Q2  (sections A,B)
Q726  TRN
Q727  RN4907_Q2  (sections A,B)
Q728  TRN
Q729  RN4907_Q2  (sections A,B)
Q819  TRN
Q820  RN4907_Q2  (sections A,B)
Q821  TRN
Q822  RN4907_Q2  (sections A,B)
R702  R
R707  R
R712  R
R717  R
R740  R
R741  R
R742  R
R743  R
R744  R
R745  R
R746  R
R747  R
R748  R
R749  R
R750  R
R751  R
R752  R
R753  R
R754  R
R755  R
R756  R
R757  R
R758  R
R759  R
R840  R
R841  R
R842  R
R843  R
R844  R
R845  R
R846  R
R847  R
R848  R
R849  R
R850  R
R851  R
R852  R
R853  R
R854  R
R855  R
R856  R
R857  R
R858  R
R859  R
R902  R
R907  R
R912  R
R917  R
R940  R
R941  R
R942  R
R943  R
R944  R
R945  R
R946  R
R947  R
R948  R
R949  R
R950  R
R951  R
R952  R
R953  R
R954  R
R955  R
R956  R
R957  R
R959  R
U?#2  WAKU_DEF_A3
sheet 11
C750  C
C751  C
C752  C
C753  C
C754  C
C756  C
C757  C
C758  C
C760  C
C761  C
C762  C
C763  C
C764  C
C765  C
C766  C
C767  C
C768  C
C843  C
C888  C
C889  C
C930  C
C931  C
C933  C
C934  C
C935  C
C936  C
C937  C
C938  C
C939  C
CN307  B2P-VH
CN308  B2P-VH
CN924  C2A
CN925  TP
CN926  C2A
CN927  C2A
CN928  TP
CN929  C2A
CN936  B2P-VH
CN937  C2A
CN938  TP
CN939  C2A
D731  DEW
D732  DEW
D813  DEW
IC730  TLVH431AQDBVRQ1
IC731  TLVH431AQDBVRQ1
IC732  TLVH431AQDBVRQ1
IC733  INA290A2QDCKRQ1
IC734  INA290A2QDCKRQ1
IC735  TS5A3159QDBVRQ1
IC736  INA290A2QDCKRQ1
IC737  INA290A2QDCKRQ1
IC738  TS5A3159QDBVRQ1
IC739  TLVH431AQDBVRQ1
IC823  TLVH431AQDBVRQ1
IC824  TLVH431AQDBVRQ1
IC825  INA290A2QDCKRQ1
IC826  INA290A2QDCKRQ1
IC827  TS5A3159QDBVRQ1
IC828  TS5A3159QDBVRQ1
Q731  TRN
Q732  RN4907_Q2  (sections A,B)
Q733  TRN
Q734  RN4907_Q2  (sections A,B)
Q736  TRN
Q737  RN4907_Q2  (sections A,B)
Q738  TRN
Q739  RN4907_Q2  (sections A,B)
Q823  TRN
Q824  RN4907_Q2  (sections A,B)
Q825  TRN
Q826  RN4907_Q2  (sections A,B)
R703  R
R708  R
R713  R
R718  R
R760  R
R761  R
R762  R
R763  R
R764  R
R765  R
R766  R
R767  R
R768  R
R769  R
R770  R
R771  R
R772  R
R773  R
R774  R
R775  R
R776  R
R777  R
R778  R
R779  R
R860  R
R861  R
R862  R
R863  R
R864  R
R865  R
R866  R
R867  R
R868  R
R869  R
R870  R
R871  R
R872  R
R873  R
R874  R
R875  R
R876  R
R877  R
R878  R
R879  R
R903  R
R908  R
R913  R
R918  R
R960  R
R961  R
R962  R
R963  R
R964  R
R965  R
R966  R
R967  R
R968  R
R969  R
R970  R
R971  R
R972  R
R973  R
R974  R
R975  R
R976  R
R977  R
R979  R
U?#1  WAKU_DEF_A3
sheet 12
C770  C
C771  C
C772  C
C773  C
C775  C
C776  C
C777  C
C778  C
C780  C
C781  C
C782  C
C783  C
C784  C
C785  C
C786  C
C787  C
C788  C
C869  C
C890  C
C891  C
C940  C
C941  C
C943  C
C944  C
C945  C
C946  C
C947  C
C948  C
C949  C
CN407  B2P-VH
CN408  B2P-VH
CN930  C2A
CN931  TP
CN932  C2A
CN933  C2A
CN934  TP
CN935  C2A
CN940  B2P-VH
CN941  C2A
CN942  TP
CN943  C2A
D741  DEW
D742  DEW
D912  DEW
IC740  TLVH431AQDBVRQ1
IC741  TLVH431AQDBVRQ1
IC742  TLVH431AQDBVRQ1
IC743  INA290A2QDCKRQ1
IC744  INA290A2QDCKRQ1
IC745  TS5A3159QDBVRQ1
IC746  INA290A2QDCKRQ1
IC747  INA290A2QDCKRQ1
IC748  TS5A3159QDBVRQ1
IC749  TLVH431AQDBVRQ1
IC829  TLVH431AQDBVRQ1
IC830  TLVH431AQDBVRQ1
IC831  INA290A2QDCKRQ1
IC832  INA290A2QDCKRQ1
IC833  TS5A3159QDBVRQ1
IC834  TS5A3159QDBVRQ1
Q741  TRN
Q742  RN4907_Q2  (sections A,B)
Q743  TRN
Q744  RN4907_Q2  (sections A,B)
Q746  TRN
Q747  RN4907_Q2  (sections A,B)
Q748  TRN
Q749  RN4907_Q2  (sections A,B)
Q827  TRN
Q828  RN4907_Q2  (sections A,B)
Q829  TRN
Q830  RN4907_Q2  (sections A,B)
R704  R
R709  R
R714  R
R719  R
R780  R
R781  R
R782  R
R783  R
R784  R
R785  R
R786  R
R787  R
R788  R
R789  R
R790  R
R791  R
R792  R
R793  R
R794  R
R795  R
R796  R
R797  R
R798  R
R799  R
R880  R
R881  R
R882  R
R883  R
R884  R
R885  R
R886  R
R887  R
R888  R
R889  R
R890  R
R891  R
R892  R
R893  R
R894  R
R895  R
R896  R
R897  R
R898  R
R899  R
R904  R
R909  R
R914  R
R919  R
R980  R
R981  R
R982  R
R983  R
R984  R
R985  R
R986  R
R987  R
R988  R
R989  R
R990  R
R991  R
R992  R
R993  R
R994  R
R995  R
R996  R
R997  R
R999  R
U?#12  WAKU_DEF_A3

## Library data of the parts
C821-C824 = CP: CDBNAME: C; COMP: C; COMPONENTTYPE: 4; VAL1: 47uF(M); VAL2: 16V
C716-C718 C726-C728 C736-C738 C746-C748 C756-C758 C766-C768 C776-C778 C786-C788 C804 C825-C828 C916-C919 C926-C929 C936-C939 C946-C949 = C: COMPONENTTYPE: 4; SIZECODESMD: 1608; VAL1: 0.1uF(K); VAL2: 50V
C829-C832 = C: COMPONENTTYPE: 4; SIZECODESMD: 2012; VAL1: 4.7uF(K); VAL2: 16V
CN960 = TP: CDBNAME: CN; COMP: CN; COMPONENTTYPE: 4; VAL3: HW-1-S
CP1-CP16 = TP: CDBNAME: CP; COMP: CP; COMPONENTTYPE: 4; NOTMOUNT: NOT MOUNT
IC803-IC806 = BD750L2FP3: CDBNAME: IC; COMP: IC; COMPONENTTYPE: 4
J801 J802 J806-J814 J817 J818 J820 J823 J828 = R: CDBNAME: JP; COMP: JP; COMPONENTTYPE: 4; SIZECODESMD: 1608; VAL1: 0
L802-L821 = L: COMPONENTTYPE: 4; VAL1: 100uH(M); VAL2: 1.3A; VAL3: CLF12555T-101M-D
U?#5 = WAKU_DEF_A3: AUTHOR: sptcae13; COMPONENTTYPE: 2; DATE: 2025/02/21; DRAWINGNUMBER: RD210-SCHEMATIC2-01; FUNCTION: Linear Regulator; REVISION: 01; SAVECOUNT: 8; SHEETNUMBER: 7/12; SHTSAVECOUNT: 20; TIME: 11:07:30; TITLE: Automotive 3kW 48V-12V Bidirectional / DC-DC Converter; UPDATEDATE: 2025.2.21; UPDATETIME: 06:47:03
C800 C801 = C: COMPONENTTYPE: 4; SIZECODESMD: 1608; VAL1: 1000pF(K); VAL2: 100V
C802 C803 C809 = C: COMPONENTTYPE: 4; SIZECODESMD: 2012; VAL1: 1uF(K); VAL2: 50V
C805 = C: COMPONENTTYPE: 4; SIZECODESMD: 1608; VAL1: 10nF(K); VAL2: 50V
C806 = C: COMPONENTTYPE: 4; SIZECODESMD: 1608; VAL1: 22pF(J); VAL2: 50V
C807 = C: COMPONENTTYPE: 4; SIZECODESMD: 1608; VAL1: 15nF(K); VAL2: 50V
C808 C816 C818 = C: COMPONENTTYPE: 4; SIZECODESMD: 3216; VAL1: 10uF(K); VAL2: 50V
C810 C811 C836 C837 = C: COMPONENTTYPE: 4; SIZECODESMD: 6050; VAL1: 22uF(K); VAL2: 100V
C812 C814 = C: COMPONENTTYPE: 4; SIZECODESMD: 3216; VAL1: 0.1uF(K); VAL2: 100V
C813 = C: COMPONENTTYPE: 4; SIZECODESMD: 1608; VAL1: 4.7nF(K); VAL2: 50V
C815 = C: COMPONENTTYPE: 4; SIZECODESMD: 1608; VAL1: 22nF(K); VAL2: 50V
C817 = C: COMPONENTTYPE: 4; SIZECODESMD: 1608; VAL1: 1uF(K); VAL2: 25V
C819 C820 = C: COMPONENTTYPE: 4; SIZECODESMD: 1608; VAL1: 470pF(J); VAL2: 50V
CN6 = C2A: CDBNAME: CN; COMP: CN; COMPONENTTYPE: 4; VAL3: B2B-XH-A
CN7 = C3A: CDBNAME: CN; COMP: CN; COMPONENTTYPE: 4; VAL3: B3B-XH-A
CN400 CN501 CN503 CN504 CN506 CN511 CN513 CN514 CN516 CN911 CN913 CN921 CN923 CN924 CN926 CN927 CN929 CN930 CN932 CN933 CN935 CN937 CN939 CN941 CN943 CN945 CN962 = C2A: CDBNAME: CN; COMP: CN; COMPONENTTYPE: 4; VAL3: TSM-102-01-L-SV
CN502 CN505 CN512 CN515 CN912 CN922 CN925 CN928 CN931 CN934 CN938 CN942 CN952-CN956 CN961 = TP: CDBNAME: CN; COMP: CN; COMPONENTTYPE: 4; VAL3: TSW-101-07-G-S
D800-D807 D811 = D: COMPONENTTYPE: 4; USERCOMPTEXT3: TOSHIBA; VAL3: CMH01
D808 = ZD: CDBNAME: D; COMP: D; COMPONENTTYPE: 4; USERCOMPTEXT3: TOSHIBA; VAL3: CRY82
D809 D810 = D: COMPONENTTYPE: 4; USERCOMPTEXT3: TOSHIBA; VAL3: 1SS307E
IC800 = LM5001IDQ1: CDBNAME: IC; COMP: IC; COMPONENTTYPE: 4
IC801 = LM5010AQ1MH: CDBNAME: IC; COMP: IC; COMPONENTTYPE: 4
IC802 = MAX6765TTLD2: CDBNAME: IC; COMP: IC; COMPONENTTYPE: 4; SAVECOUNT: 8
L800 = L: COMPONENTTYPE: 4; VAL1: 33uH(M); VAL2: 1.1A; VAL3: LAYPH06045DL330MGA
L801 = L: COMPONENTTYPE: 4; VAL1: 560uH(K); VAL2: 1.0A; VAL3: MSS1278H-564K_D
Q711 Q713 Q716 Q718 Q721 Q723 Q726 Q728 Q731 Q733 Q736 Q738 Q741 Q743 Q746 Q748 Q801 Q802 Q815 Q817 Q819 Q821 Q823 Q825 Q827 Q829 = TRN: CDBNAME: Q; COMP: Q; COMPONENTTYPE: 4; USERCOMPTEXT3: TOSHIBA; VAL3: 2SC4117-GR
R800 = R: COMPONENTTYPE: 4; SIZECODESMD: 1608; VAL1: 27k(F); VAL2: 200mW
R801 = R: COMPONENTTYPE: 4; SIZECODESMD: 1608; VAL1: 100k(F); VAL2: 200mW
R802 R803 R810 R811 = R: COMPONENTTYPE: 4; SIZECODESMD: 1608; VAL1: 22k(F); VAL2: 333mW
R804 = R: COMPONENTTYPE: 4; SIZECODESMD: 1608; VAL1: 10k(F); VAL2: 200mW
R805 R806 = R: COMPONENTTYPE: 4; SIZECODESMD: 1608; VAL1: 18k(F); VAL2: 200mW
R807 = R: COMPONENTTYPE: 4; SIZECODESMD: 2012; VAL1: 10(J); VAL2: 500mW
R808 = R: COMPONENTTYPE: 4; SIZECODESMD: 1608; VAL1: 12k(D); VAL2: 200mW
R809 = R: COMPONENTTYPE: 4; SIZECODESMD: 1608; VAL1: 1k(D); VAL2: 200mW
R812 = R: COMPONENTTYPE: 4; SIZECODESMD: 1608; VAL1: 430k(F); VAL2: 200mW
R813 = R: COMPONENTTYPE: 4; SIZECODESMD: 1608; VAL1: 1.6(F); VAL2: 333mW
R814 = R: COMPONENTTYPE: 4; SIZECODESMD: 1608; VAL1: 6.8k(D); VAL2: 200mW
R815 = R: COMPONENTTYPE: 4; SIZECODESMD: 1608; VAL1: 1.8k(D); VAL2: 200mW
R816 = R: COMPONENTTYPE: 4; SIZECODESMD: 2012; VAL1: 100(J); VAL2: 250mW
R817 = R: COMPONENTTYPE: 4; SIZECODESMD: 1608; VAL1: 1.8k(F); VAL2: 333mW
R818 = R: COMPONENTTYPE: 4; SIZECODESMD: 1608; VAL1: 8.2k(F); VAL2: 333mW
R819 R900 = R: COMPONENTTYPE: 4; SIZECODESMD: 1608; VAL1: 10(D); VAL2: 100mW
TP801 TP802 TP805 = TP: COMPONENTTYPE: 4; VAL3: HW-1-S
TP803 = TP: COMPONENTTYPE: 4; VAL3: TSW-101-07-G-S
U?#4 = WAKU_DEF_A3: COMPONENTTYPE: 2; DATE: 2025/02/21; DRAWINGNUMBER: RD210-SCHEMATIC2-01; FUNCTION: Switching Regulator 2; REVISION: 01; SAVECOUNT: 19; SHEETNUMBER: 8/12; SHTSAVECOUNT: 97; TITLE: Automotive 3kW 48V-12V Bidirectional / DC-DC Converter; UPDATEDATE: 2025.2.21; UPDATETIME: 09:54:20
C710 C711 C720 C721 C730 C731 C740 C741 C750 C751 C760 C761 C770 C771 C780 C781 C910 C911 C920 C921 C930 C931 C940 C941 = C: COMPONENTTYPE: 4; NOTMOUNT: NOT MOUNT; SIZECODESMD: 1608; VAL1: 0.1uF(K); VAL2: 50V
C712 C722 C732 C742 C752 C762 C772 C782 = C: COMPONENTTYPE: 4; SIZECODESMD: 3216; VAL1: 0.047uF(J); VAL2: 50V
C713 C723 C733 C743 C753 C763 C773 C783 = C: COMPONENTTYPE: 4; SIZECODESMD: 1608; VAL1: 33nF(K); VAL2: 50V
C714 C715 C724 C725 C734 C735 C744 C745 C754 C764 C765 C775 C784 C785 C843 C869 C913-C915 C923-C925 C933-C935 C943-C945 = C: COMPONENTTYPE: 4; SIZECODESMD: 1608; VAL1: 4.7nF(J); VAL2: 50V
C719 C729 C886-C891 = C: COMPONENTTYPE: 4; NOTMOUNT: NOT MOUNT; SIZECODESMD: 1608; VAL1: 4.7nF(J); VAL2: 50V
CN208 CN307 CN308 CN407 CN408 CN508 CN509 CN618 CN910 CN920 CN936 CN940 = B2P-VH: CDBNAME: CN; COMP: CN; COMPONENTTYPE: 4
D711-D713 D721 D722 D731 D732 D741 D742 D812 D813 D912 = DEW: CDBNAME: D; COMP: D; COMPONENTTYPE: 4; USERCOMPTEXT3: TOSHIBA; VAL3: 1SS362FV
IC710-IC712 IC719-IC722 IC729-IC732 IC739-IC742 IC749 IC811 IC812 IC817 IC818 IC823 IC824 IC829 IC830 = TLVH431AQDBVRQ1: CDBNAME: IC; COMP: IC; COMPONENTTYPE: 4
IC713 IC714 IC716 IC717 IC723 IC724 IC726 IC727 IC733 IC734 IC736 IC737 IC743 IC744 IC746 IC747 IC813 IC814 IC819 IC820 IC825 IC826 IC831 IC832 = INA290A2QDCKRQ1: CDBNAME: IC; COMP: IC; COMPONENTTYPE: 4
IC715 IC718 IC725 IC728 IC735 IC738 IC745 IC748 IC815 IC816 IC821 IC822 IC827 IC828 IC833 IC834 = TS5A3159QDBVRQ1: CDBNAME: IC; COMP: IC; COMPONENTTYPE: 4
Q712 Q717 Q724 Q732 Q818 Q820 = RN4907_Q2: CDBNAME: RN4907; COMP: RN4907; COMPONENTNAME: RN4907_1; COMPONENTTYPE: 8; CaptureCellPackProp: RN4907_Q2A; FUNCN: RN4907_1; USERCOMPTEXT1: 1/2; VAL3: RN4907; USERCOMPTEXT3: TOSHIBA
Q714 Q722 Q744 Q749 = RN4907_Q2: CDBNAME: RN4907; COMP: RN4907; COMPONENTNAME: RN4907_2; COMPONENTTYPE: 8; CaptureCellPackProp: RN4907_Q2B; FUNCN: RN4907_2; USERCOMPTEXT1: 2/2; VAL3: RN4907; USERCOMPTEXT3: TOSHIBA
Q719 Q727 Q729 Q734 Q737 Q739 Q747 Q816 Q822 Q824 Q826 = RN4907_Q2: CDBNAME: RN4907; COMP: RN4907; COMPONENTNAME: RN4907_1; COMPONENTTYPE: 8; CaptureCellPackProp: RN4907_Q2A; FUNCN: RN4907_1; USERCOMPTEXT1: 1/2; USERCOMPTEXT3: TOSHIBA; VAL3: RN4907
R701-R704 R711-R714 R716-R719 R901-R904 R911-R914 R916-R919 = R: COMPONENTTYPE: 4; SIZECODESMD: 1608; VAL1: 0
R706-R709 R736-R738 R756-R758 R776-R778 R796-R798 R836-R838 R856-R858 R876-R878 R896-R898 R906-R909 R936 R937 R956 R957 R976 R977 R996 R997 = R: COMPONENTTYPE: 4; SIZECODESMD: 1608; VAL1: 47(F); VAL2: 125mW
R720 R721 R740 R741 R760 R761 R780 R781 R820 R821 R840 R841 R860 R861 R880 R881 R920 R921 R940 R941 R960 R961 R980 R981 = R: COMPONENTTYPE: 4; NOTMOUNT: NOT MOUNT; SIZECODESMD: 1608; VAL1: 1k(F); VAL2: 100mW
R722 R723 R742 R743 R762 R763 R782 R783 R822 R823 R842 R843 R862 R863 R882 R883 R922 R923 R942 R943 R962 R963 R982 R983 = R: COMPONENTTYPE: 4; SIZECODESMD: 1608; VAL1: 22k(F); VAL2: 100mW
R724-R727 R744-R747 R764-R767 R784-R787 R824-R827 R844-R847 R864-R867 R884-R887 R924-R927 R944-R947 R964-R967 R984-R987 = R: COMPONENTTYPE: 4; SIZECODESMD: 1608; VAL1: 1k(F); VAL2: 125mW
R728 R729 R748 R749 R768 R769 R788 R789 R828 R829 R848 R849 R868 R869 R888 R889 R928 R929 R948 R949 R968 R969 R988 R989 = R: COMPONENTTYPE: 4; SIZECODESMD: 1608; VAL1: 2.7k(F); VAL2: 100mW
R730-R733 R750-R753 R770-R773 R790-R793 R830-R833 R850-R853 R870-R873 R890-R893 R930-R933 R950-R953 R970-R973 R990-R993 = R: COMPONENTTYPE: 4; SIZECODESMD: 3216; VAL1: 10(J); VAL2: 250mW
R734 R735 R754 R755 R774 R775 R794 R795 R834 R835 R854 R855 R874 R875 R894 R895 R934 R935 R954 R955 R974 R975 R994 R995 = R: COMPONENTTYPE: 4; SIZECODESMD: 1608; VAL1: 10k(J); VAL2: 100mW
R739 R759 R779 R799 R839 R859 R879 R899 R939 R959 R979 R999 = R: COMPONENTTYPE: 4; NOTMOUNT: NOT MOUNT; SIZECODESMD: 1608; VAL1: 10(F); VAL2: 100mW
U?#3 = WAKU_DEF_A3: COMPONENTTYPE: 2; DATE: 2025/02/21; DRAWINGNUMBER: RD210-SCHEMATIC2-01; FUNCTION: Current Sensing Circuit(BLOCK 0); REVISION: 01; SHEETNUMBER: 9/12; SHTSAVECOUNT: 140; TITLE: Automotive 3kW 48V-12V Bidirectional / DC-DC Converter; UPDATEDATE: 2025.2.21; UPDATETIME: 06:47:03
U?#2 = WAKU_DEF_A3: COMPONENTTYPE: 2; DATE: 2025/02/21; DRAWINGNUMBER: RD210-SCHEMATIC2-01; FUNCTION: Current Sensing Circuit(BLOCK 1); REVISION: 01; SHEETNUMBER: 10/12; SHTSAVECOUNT: 173; TITLE: Automotive 3kW 48V-12V Bidirectional / DC-DC Converter; UPDATEDATE: 2025.2.21; UPDATETIME: 06:49:54
U?#1 = WAKU_DEF_A3: AUTHOR: t5459927; COMPONENTTYPE: 2; DATE: 2025/02/21; DRAWINGNUMBER: RD210-SCHEMATIC2-01; FUNCTION: Current Sensing Circuit(BLOCK 2); REVISION: 01; SHEETNUMBER: 11/12; SHTSAVECOUNT: 16; TIME: 19:41:36; TITLE: Automotive 3kW 48V-12V Bidirectional / DC-DC Converter; UPDATEDATE: 2025.2.21; UPDATETIME: 06:59:19
Q742 Q828 = RN4907_Q2: CDBNAME: RN4907; COMP: RN4907; COMPONENTNAME: R4907_1; COMPONENTTYPE: 8; CaptureCellPackProp: RN4907_Q2A; FUNCN: R4907_1; USERCOMPTEXT1: 1/2; VAL3: RN4907; USERCOMPTEXT3: TOSHIBA
Q830 = RN4907_Q2: CDBNAME: RN4907; COMP: RN4907; COMPONENTNAME: R4907_1; COMPONENTTYPE: 8; CaptureCellPackProp: RN4907_Q2A; FUNCN: R4907_1; USERCOMPTEXT1: 1/2; USERCOMPTEXT3: TOSHIBA; VAL3: RN4907
U?#12 = WAKU_DEF_A3: AUTHOR: t5459927; COMPONENTTYPE: 2; DATE: 2025/02/21; DRAWINGNUMBER: RD210-SCHEMATIC2-01; FUNCTION: Current Sensing Circuit(BLOCK 3); REVISION: 01; SHEETNUMBER: 12/12; SHTSAVECOUNT: 14; TIME: 19:44:08; TITLE: Automotive 3kW 48V-12V Bidirectional / DC-DC Converter; UPDATEDATE: 2025.2.21; UPDATETIME: 14:01:10

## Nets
GND: C801.1 C812.1 C813.1 C814.2 C816.1 C817.1 C818.1 C819.1 C820.1 C836.1 C837.1 CN400.2 CN955.1 CN956.1 IC801.5 IC801.6 IC801.15 IC802.2 IC802.7 Q801.2(E) Q802.2(E) R803.1 R811.1 R815.1 ; also on sheet 7 8 9 10 11 12
GND-1: C716.1 C716.2 C717.1 C717.2 C718.1 C718.2 C726.1 C726.2 C727.1 C727.2 C728.1 C728.2 C736.1 C736.2 C737.1 C737.2 C738.1 C738.2 C746.1 C746.2 C747.1 C747.2 C748.1 C748.2 C756.1 C756.2 C757.1 C757.2 C758.1 C758.2 C766.1 C766.2 C767.1 C767.2 C768.1 C768.2 C776.1 C776.2 C777.1 C777.2 C778.1 C778.2 C786.1 C786.2 C787.1 C787.2 C788.1 C788.2 C916.1 C916.2 C917.1 C917.2 C918.1 C918.2 C919.1 C919.2 C926.1 C926.2 C927.1 C927.2 C928.1 C928.2 C929.1 C929.2 C936.1 C936.2 C937.1 C937.2 C938.1 C938.2 C939.1 C939.2 C946.1 C946.2 C947.1 C947.2 C948.1 C948.2 C949.1 C949.2 CN502.1 CN505.1 CN512.1 CN515.1 CN912.1 CN922.1 CN925.1 CN928.1 CN931.1 CN934.1 CN938.1 CN942.1 D711.1(A) D712.1(A) D713.1(A) D721.1(A) D722.1(A) D731.1(A) D732.1(A) D741.1(A) D742.1(A) D812.1(A) D813.1(A) D912.1(A) IC710.5 IC711.5 IC712.5 IC713.2 IC713.3 IC714.2 IC714.3 IC715.2 IC715.5 IC716.2 IC716.3 IC717.2 IC717.3 IC718.2 IC718.5 IC719.5 IC720.5 IC721.5 IC722.5 IC723.2 IC723.3 IC724.2 IC724.3 IC725.2 IC725.5 IC726.2 IC726.3 IC727.2 IC727.3 IC728.2 IC728.5 IC729.5 IC730.5 IC731.5 IC732.5 IC733.2 IC733.3 IC734.2 IC734.3 IC735.2 IC735.5 IC736.2 IC736.3 IC737.2 IC737.3 IC738.2 IC738.5 IC739.5 IC740.5 IC741.5 IC742.5 IC743.2 IC743.3 IC744.2 IC744.3 IC745.2 IC745.5 IC746.2 IC746.3 IC747.2 IC747.3 IC748.2 IC748.5 IC749.5 IC811.5 IC812.5 IC813.2 IC813.3 IC814.2 IC814.3 IC815.2 IC815.5 IC816.2 IC816.5 IC817.5 IC818.5 IC819.2 IC819.3 IC820.2 IC820.3 IC821.2 IC821.5 IC822.2 IC822.5 IC823.5 IC824.5 IC825.2 IC825.3 IC826.2 IC826.3 IC827.2 IC827.5 IC828.2 IC828.5 IC829.5 IC830.5 IC831.2 IC831.3 IC832.2 IC832.3 IC833.2 IC833.5 IC834.2 IC834.5 Q712.1 Q712.4 Q714.1 Q714.4 Q717.1 Q717.4 Q719.1 Q719.4 Q722.1 Q722.4 Q724.1 Q724.4 Q727.1 Q727.4 Q729.1 Q729.4 Q732.1 Q732.4 Q734.1 Q734.4 Q737.1 Q737.4 Q739.1 Q742.1 Q742.4 Q744.1 Q744.4 Q747.1 Q747.4 Q749.1 Q749.4 Q816.1 Q816.4 Q818.1 Q818.4 Q820.1 Q820.4 Q822.1 Q822.4 Q824.1 Q824.4 Q826.1 Q826.4 Q828.1 Q830.1 R728.1 R729.1 R734.2 R735.2 R748.1 R749.1 R754.2 R755.2 R768.1 R769.1 R774.2 R775.2 R788.1 R789.1 R794.2 R795.2 R828.1 R829.1 R834.2 R835.2 R848.1 R849.1 R854.2 R855.2 R868.1 R869.1 R874.2 R875.2 R888.1 R889.1 R894.2 R895.2 R928.1 R929.1 R934.2 R935.2 R948.1 R949.1 R954.2 R955.2 R968.1 R969.1 R974.2 R975.2 R988.1 R989.1 R994.2 R995.2 ; also on sheet 7
GND-1 (page 11): Q739.4
GND-1 (page 12): Q828.4 Q830.4
GND_P0: C802.1 C803.1 C804.1 C805.2 C808.1 C809.1 C810.1 C811.1 C821.2(1) C825.1 C829.1 CN7.3 CN953.1 CN960.1 D808.1(A) IC800.4 IC803.2 R804.2 R805.1 R809.1 ; also on sheet 8
GND_P1: C822.2(1) C826.1 C830.1 IC804.2 ; also on sheet 8
GND_P2: C823.2(1) C827.1 C831.1 IC805.2 ; also on sheet 8
GND_P3: C824.2(1) C828.1 C832.1 IC806.2 ; also on sheet 8
VDDA: D711.2(C) D712.2(C) D713.2(C) D721.2(C) D722.2(C) D731.2(C) D732.2(C) D741.2(C) D742.2(C) D812.2(C) D813.2(C) D912.2(C) ; also on sheet 7 8 12
BIAS_1_ON-1: Q714.5 Q717.5 Q816.5 ; also on sheet 12
BIAS_1_ON-2: Q724.5 Q727.5 Q820.5 ; also on sheet 10
BIAS_1_ON-3: Q734.5 Q737.5 Q824.5 ; also on sheet 11
BIAS_1_ON-4: Q744.5 Q747.5 Q828.5 ; also on sheet 11
BIAS_2_ON-1: Q712.5 Q719.5 Q818.5 ; also on sheet 12
BIAS_2_ON-2: Q722.5 Q729.5 Q822.5 ; also on sheet 10
BIAS_2_ON-3: Q732.5 Q739.5 Q826.5 ; also on sheet 11
BIAS_2_ON-4: Q742.5 Q749.5 Q830.5 ; also on sheet 11
I_C0-1: IC816.3 R937.2
I_C0-2: IC822.3 R957.2
I_C0-3: IC828.3 R977.2
I_C0-4: IC834.3 R997.2
I_H0-1: D713.3(AC) R906.2 ; also on sheet 12
I_H0-2: D812.3(AC) R907.2 ; also on sheet 12
I_H0-3: D813.3(AC) R908.2 ; also on sheet 12
I_H0-4: D912.3(AC) R909.2 ; also on sheet 12
I_H0_B-1: D711.3(AC) IC816.1 R737.2
I_H0_B-2: D721.3(AC) IC822.1 R757.2
I_H0_B-3: D731.3(AC) IC828.1 R777.2
I_H0_B-4: D741.3(AC) IC834.1 R797.2
I_L0-1: D712.3(AC) R837.2 ; also on sheet 12
I_L0-2: D722.3(AC) R857.2 ; also on sheet 12
I_L0-3: D732.3(AC) R877.2 ; also on sheet 12
I_L0-4: D742.3(AC) R897.2 ; also on sheet 12
I_SEL_1: R736.2 R836.2 R936.2 ; also on sheet 9
I_SEL_2: R756.2 R856.2 R956.2 ; also on sheet 9
I_SEL_3: R776.2 R876.2 R976.2 ; also on sheet 9
I_SEL_4: R796.2 R896.2 R996.2 ; also on sheet 9
I_SEL_CM-1: R706.2 ; also on sheet 12
I_SEL_CM-2: R707.2 ; also on sheet 11
I_SEL_CM-3: R708.2 ; also on sheet 11
I_SEL_CM-4: R709.2 ; also on sheet 10
SIG0083: C817.2 IC801.12
SIG0084: C813.2 IC801.10
SIG0085: D807.1(A) IC801.4
SIG0087: C815.2 D807.2(C) IC801.2 L801.1
SIG0093: C712.1 C713.1 C719.1 CN508.1 R730.1 R732.1 R739.2
SIG0096: CN503.2 IC715.3 R901.2
SIG0099: Q711.2(E) R726.1 R728.2
SIG0101: CN513.2 IC725.3 R902.2
SIG0102: Q721.1(B) R744.1
SIG0103: C730.1 R740.2
SIG0104: C735.2 IC724.4 R752.2
SIG0105: C734.2 IC723.4 R751.2
SIG0106: CN511.2 IC725.1 R702.2
SIG0107: IC725.4 R757.1
SIG0108: IC725.6 R756.1
SIG0109: IC721.4 R740.1 R746.2
SIG0111: CN927.1 IC736.1 R713.1 R874.1
SIG0112: C760.1 R860.2
SIG0113: IC731.4 R760.1 R766.2
SIG0114: Q738.1(B) R865.1
SIG0115: CN924.2 IC735.1 R703.2
SIG0116: CN929.1 IC737.1 R875.1 R913.1
SIG0117: C754.2 IC733.4 R771.2
SIG0118: Q824.2 Q824.3
SIG0119: C750.1 R760.2
SIG0121: Q830.2 Q830.3
SIG0122: Q742.6 R782.2
SIG0123: IC749.4 R880.1 R886.2
SIG0124: C775.1 IC744.5 Q743.3(C) R793.1
SIG0125: Q746.1(B) R884.1
SIG0126: C941.2 IC830.3 R983.1 R985.2
SIG0127: Q827.2(E) R986.1 R988.2
SIG0128: IC833.4 R997.1
SIG0129: C945.2 IC832.4 R992.2
SIG00810: C815.1 IC801.3
SIG00814: C809.2 D810.2(C) IC800.3 R801.1
SIG00815: C810.2 C811.2 CN945.1 CN954.1 D806.2(C) J818.1 R900.2
SIG00816: C805.1 D808.2(C) IC800.8 Q801.3(C) R804.1 R806.2
SIG00818: J828.1 R817.2
SIG00819: C820.2 R802.1 R810.1 R816.2 R818.1
SIG00911: Q711.1(B) R724.1
SIG00913: C710.1 R720.2
SIG00915: C715.2 IC714.4 R732.2
SIG00919: C719.2 CN508.2 R738.1 R739.1
SIG00920: C714.2 IC713.4 R731.2
SIG00922: CN501.1 IC713.1 R701.1 R734.1
SIG00923: C714.1 IC713.5 Q711.3(C) R730.2
SIG924: CP1.1 J806.2 L802.1
SIG00924: CN501.2 IC715.1 R701.2
SIG926: C829.2 CP3.1 IC803.3 J814.1
SIG927: CP4.1 J814.2 L810.1 L811.1 L812.1
SIG00927: IC711.4 R720.1 R726.2
SIG929: CP2.1 J807.2 L806.1
SIG930: CP6.1 J809.2 L807.1
SIG00930: C710.2 IC711.3 R722.1 R724.2
SIG931: C830.2 CP7.1 IC804.3 J817.1
SIG932: CP8.1 J817.2 L813.1 L814.1 L815.1
SIG933: CP5.1 J808.2 L803.1
SIG934: CP10.1 J811.2 L808.1
SIG935: C832.2 CP15.1 IC806.3 J823.1
SIG936: C831.2 CP11.1 IC805.3 J820.1
SIG937: CP12.1 J820.2 L816.1 L817.1 L818.1
SIG938: CP14.1 J813.2 L809.1
SIG939: CP9.1 J810.2 L804.1
SIG940: CP13.1 J812.2 L805.1
SIG941: CP16.1 J823.2 L819.1 L820.1 L821.1
SIG00941: C712.2 C713.2 R731.1 R733.2 R738.2
SIG946: C802.2 C803.2 D800.2(C) D801.2(C) D802.2(C) D803.2(C) D804.2(C) L800.1 R807.2 TP801.1
SIG947: C804.2 IC800.2 R806.1 R807.1
SIG948: CN952.1 D806.1(A) IC800.1 L800.2
SIG950: IC800.5 R805.2
SIG00952: IC715.4 R737.1
SIG00953: IC715.6 R736.1
SIG954: C806.2 C807.2 D809.1(A) IC800.7
SIG955: C807.1 R800.2
SIG957: CN945.2 R808.2 R900.1
SIG960: C812.2 C836.2 C837.2 D805.2(C) D811.2(C) IC801.13 J801.2 R812.1 TP803.1
SIG961: D811.1(A) J818.2
SIG964: C816.2 CN961.1 IC802.5 IC802.6 J828.2
SIG965: Q801.1(B) R802.2 R803.2
SIG967: C819.2 R817.1 R818.2
SIG968: C800.1 C801.2
SIG969: C800.2 CN400.1 R816.1
SIG980: Q802.1(B) R810.2 R811.2
SIG983: IC801.11 Q802.3(C) R812.2
SIG984: C818.2 R813.1
SIG985: IC801.9 R814.1 R815.2
SIG986: CN962.2 R814.2 R819.1
SIG987: CN962.1 J802.1 L801.2 R813.2 R819.2 TP805.1
SIG00989: Q712.6 R722.2
SIG01010: Q722.6 R742.2
SIG01011: CN511.1 IC723.1 R702.1 R754.1
SIG01012: CN513.1 IC724.1 R755.1 R902.1
SIG01013: C730.2 IC721.3 R742.1 R744.2
SIG01014: Q721.2(E) R746.1 R748.2
SIG01015: Q722.2 Q722.3
SIG01016: Q724.2 Q724.3
SIG01017: C731.2 IC722.3 R743.1 R745.2
SIG01018: IC722.4 R741.1 R747.2
SIG01019: C731.1 R741.2
SIG01020: Q724.6 R743.2
SIG01021: Q723.2(E) R747.1 R749.2
SIG01022: Q723.1(B) R745.1
SIG01023: C735.1 IC724.5 Q723.3(C) R753.1
SIG01024: C734.1 IC723.5 Q721.3(C) R750.2
SIG01025: C886.2 CN618.2 R758.1 R759.1
SIG01026: C732.2 C733.2 R751.1 R753.2 R758.2
SIG01027: C732.1 C733.1 C886.1 CN618.1 R750.1 R752.1 R759.2
SIG01028: CN514.1 IC726.1 R712.1 R854.1
SIG01029: IC728.6 R856.1
SIG01030: C741.2 IC720.3 R843.1 R845.2
SIG01031: IC728.4 R857.1
SIG01032: C740.1 R840.2
SIG01033: C745.1 IC727.5 Q728.3(C) R853.1
SIG01034: C744.2 IC726.4 R851.2
SIG01035: CN516.1 IC727.1 R855.1 R912.1
SIG01036: Q726.1(B) R844.1
SIG01037: Q728.1(B) R845.1
SIG01038: Q729.6 R843.2
SIG01039: C741.1 R841.2
SIG01040: IC720.4 R841.1 R847.2
SIG01041: C745.2 IC727.4 R852.2
SIG01042: Q726.2(E) R846.1 R848.2
SIG01043: Q727.2 Q727.3
SIG01044: C740.2 IC729.3 R842.1 R844.2
SIG01045: Q729.2 Q729.3
SIG01046: C742.2 C743.2 R851.1 R853.2 R858.2
SIG01047: Q728.2(E) R847.1 R849.2
SIG01048: C887.2 CN208.2 R858.1 R859.1
SIG01049: C744.1 IC726.5 Q726.3(C) R850.2
SIG01050: Q727.6 R842.2
SIG01051: IC729.4 R840.1 R846.2
SIG01052: C742.1 C743.1 C887.1 CN208.1 R850.1 R852.1 R859.2
SIG01053: CN516.2 IC728.1 R912.2
SIG01054: CN514.2 IC728.3 R712.2
SIG01055: Q820.2 Q820.3
SIG01056: C920.2 IC817.3 R942.1 R944.2
SIG01057: CN921.2 IC821.3 R717.2
SIG01058: C923.1 CN920.1 R950.1 R952.1 R959.2
SIG01059: Q822.2 Q822.3
SIG01060: C924.1 IC819.5 Q819.3(C) R950.2
SIG01061: Q819.2(E) R946.1 R948.2
SIG01062: Q821.2(E) R947.1 R949.2
SIG01063: Q820.6 R942.2
SIG01064: CN923.2 IC821.1 R917.2
SIG01065: IC817.4 R940.1 R946.2
SIG01066: C925.2 IC820.4 R952.2
SIG01067: C921.1 R941.2
SIG01068: Q821.1(B) R945.1
SIG01069: Q819.1(B) R944.1
SIG01070: CN923.1 IC820.1 R917.1 R955.1
SIG01071: IC818.4 R941.1 R947.2
SIG01072: Q822.6 R943.2
SIG01073: CN921.1 IC819.1 R717.1 R954.1
SIG01074: C924.2 IC819.4 R951.2
SIG01075: IC821.4 R957.1
SIG01076: C925.1 IC820.5 Q821.3(C) R953.1
SIG01077: IC821.6 R956.1
SIG01078: C921.2 IC818.3 R943.1 R945.2
SIG01079: C920.1 R940.2
SIG01080: C923.2 CN920.2 R951.1 R953.2 R959.1
SIG01081: IC822.4 R907.1
SIG01082: IC822.6 R707.1
SIG01110: IC739.4 R860.1 R866.2
SIG01111: Q736.1(B) R864.1
SIG01112: Q826.2 Q826.3
SIG01113: IC735.4 R777.1
SIG01114: CN929.2 IC738.1 R913.2
SIG01115: C762.1 C763.1 C889.1 CN308.1 R870.1 R872.1 R879.2
SIG01116: CN937.2 IC827.3 R718.2
SIG01117: CN924.1 IC733.1 R703.1 R774.1
SIG01118: IC828.6 R708.1
SIG01119: IC738.6 R876.1
SIG01120: Q731.1(B) R764.1
SIG01121: Q739.6 R863.2
SIG01122: IC730.4 R861.1 R867.2
SIG01123: IC735.6 R776.1
SIG01124: CN926.2 IC735.3 R903.2
SIG01125: CN927.2 IC738.3 R713.2
SIG01126: Q732.6 R762.2
SIG01127: IC828.4 R908.1
SIG01128: IC738.4 R877.1
SIG01129: IC732.4 R761.1 R767.2
SIG01130: C931.1 R961.2
SIG01131: CN939.1 IC826.1 R918.1 R975.1
SIG01132: Q739.2 Q739.3
SIG01133: C765.2 IC737.4 R872.2
SIG01134: C751.2 IC732.3 R763.1 R765.2
SIG01135: C843.1 IC734.5 Q733.3(C) R773.1
SIG01136: IC827.4 R977.1
SIG01137: C889.2 CN308.2 R878.1 R879.1
SIG01138: C930.1 R960.2
SIG01139: Q737.6 R862.2
SIG01140: Q733.1(B) R765.1
SIG01141: C931.2 IC824.3 R963.1 R965.2
SIG01142: C752.1 C753.1 C888.1 CN307.1 R770.1 R772.1 R779.2
SIG01143: C935.1 IC826.5 Q825.3(C) R973.1
SIG01144: IC823.4 R960.1 R966.2
SIG01145: C752.2 C753.2 R771.1 R773.2 R778.2
SIG01146: Q732.2 Q732.3
SIG01147: IC827.6 R976.1
SIG01148: C888.2 CN307.2 R778.1 R779.1
SIG01149: Q824.6 R962.2
SIG01150: C751.1 R761.2
SIG01151: Q826.6 R963.2
SIG01152: CN939.2 IC827.1 R918.2
SIG01153: Q823.1(B) R964.1
SIG01154: Q825.1(B) R965.1
SIG01155: Q734.2 Q734.3
SIG01156: C762.2 C763.2 R871.1 R873.2 R878.2
SIG01157: Q737.2 Q737.3
SIG01158: Q731.2(E) R766.1 R768.2
SIG01159: C935.2 IC826.4 R972.2
SIG01160: C764.1 IC736.5 Q736.3(C) R870.2
SIG01161: C750.2 IC731.3 R762.1 R764.2
SIG01162: Q734.6 R763.2
SIG01163: C934.2 IC825.4 R971.2
SIG01164: CN937.1 IC825.1 R718.1 R974.1
SIG01165: C760.2 IC739.3 R862.1 R864.2
SIG01166: Q733.2(E) R767.1 R769.2
SIG01167: Q738.2(E) R867.1 R869.2
SIG01168: IC824.4 R961.1 R967.2
SIG01169: Q736.2(E) R866.1 R868.2
SIG01170: C754.1 IC733.5 Q731.3(C) R770.2
SIG01171: C761.1 R861.2
SIG01172: C843.2 IC734.4 R772.2
SIG01173: C934.1 IC825.5 Q823.3(C) R970.2
SIG01174: C761.2 IC730.3 R863.1 R865.2
SIG01175: C933.1 CN936.1 R970.1 R972.1 R979.2
SIG01176: C930.2 IC823.3 R962.1 R964.2
SIG01177: Q825.2(E) R967.1 R969.2
SIG01178: C764.2 IC736.4 R871.2
SIG01179: CN926.1 IC734.1 R775.1 R903.1
SIG01180: C765.1 IC737.5 Q738.3(C) R873.1
SIG01181: Q823.2(E) R966.1 R968.2
SIG01182: C933.2 CN936.2 R971.1 R973.2 R979.1
SIG01210: IC742.4 R781.1 R787.2
SIG01211: C770.2 IC741.3 R782.1 R784.2
SIG01212: Q747.6 R882.2
SIG01213: Q744.2 Q744.3
SIG01214: C941.1 R981.2
SIG01215: Q743.1(B) R785.1
SIG01216: C940.1 R980.2
SIG01217: C770.1 R780.2
SIG01218: Q743.2(E) R787.1 R789.2
SIG01219: CN935.1 IC747.1 R895.1 R914.1
SIG01220: C943.1 CN940.1 R990.1 R992.1 R999.2
SIG01221: CN943.1 IC832.1 R919.1 R995.1
SIG01222: Q828.2 Q828.3
SIG01223: Q748.1(B) R885.1
SIG01224: C781.2 IC740.3 R883.1 R885.2
SIG01225: C891.2 CN408.2 R898.1 R899.1
SIG01226: CN930.2 IC745.1 R704.2
SIG01227: IC748.4 R897.1
SIG01228: Q829.2(E) R987.1 R989.2
SIG01229: C940.2 IC829.3 R982.1 R984.2
SIG01230: C944.1 IC831.5 Q827.3(C) R990.2
SIG01231: C771.2 IC742.3 R783.1 R785.2
SIG01232: C775.2 IC744.4 R792.2
SIG01233: CN930.1 IC743.1 R704.1 R794.1
SIG01234: C869.1 IC743.5 Q741.3(C) R790.2
SIG01235: C945.1 IC832.5 Q829.3(C) R993.1
SIG01236: C785.1 IC747.5 Q748.3(C) R893.1
SIG01237: Q830.6 R983.2
SIG01238: IC834.6 R709.1
SIG01239: C890.2 CN407.2 R798.1 R799.1
SIG01240: CN932.1 IC744.1 R795.1 R904.1
SIG01241: C772.1 C773.1 C890.1 CN407.1 R790.1 R792.1 R799.2
SIG01242: IC745.6 R796.1
SIG01243: IC829.4 R980.1 R986.2
SIG01244: IC740.4 R881.1 R887.2
SIG01245: Q746.2(E) R886.1 R888.2
SIG01246: C781.1 R881.2
SIG01247: C771.1 R781.2
SIG01248: CN932.2 IC745.3 R904.2
SIG01249: Q741.1(B) R784.1
SIG01250: CN935.2 IC748.1 R914.2
SIG01251: IC833.6 R996.1
SIG01252: Q749.6 R883.2
SIG01253: C782.1 C783.1 C891.1 CN408.1 R890.1 R892.1 R899.2
SIG01254: IC830.4 R981.1 R987.2
SIG01255: C784.2 IC746.4 R891.2
SIG01256: Q742.2 Q742.3
SIG01257: Q748.2(E) R887.1 R889.2
SIG01258: IC748.6 R896.1
SIG01259: C772.2 C773.2 R791.1 R793.2 R798.2
SIG01260: CN941.2 IC833.3 R719.2
SIG01261: CN933.1 IC746.1 R714.1 R894.1
SIG01262: C944.2 IC831.4 R991.2
SIG01263: C784.1 IC746.5 Q746.3(C) R890.2
SIG01264: Q741.2(E) R786.1 R788.2
SIG01265: Q747.2 Q747.3
SIG01266: Q828.6 R982.2
SIG01267: C943.2 CN940.2 R991.1 R993.2 R999.1
SIG01268: C782.2 C783.2 R891.1 R893.2 R898.2
SIG01269: Q749.2 Q749.3
SIG01270: Q827.1(B) R984.1
SIG01271: IC741.4 R780.1 R786.2
SIG01272: C780.2 IC749.3 R882.1 R884.2
SIG01273: C780.1 R880.2
SIG01274: Q829.1(B) R985.1
SIG01275: CN933.2 IC748.3 R714.2
SIG01276: C869.2 IC743.4 R791.2
SIG01277: CN943.2 IC833.1 R919.2
SIG01278: IC745.4 R797.1
SIG01279: IC834.4 R909.1
SIG01280: C785.2 IC747.4 R892.2
SIG01281: CN941.1 IC831.1 R719.1 R994.1
SIG01282: Q744.6 R783.2
SIG1395: C806.1 IC800.6 R800.1 R808.1 R809.2
SIG1396: C808.2 D809.2(C) D810.1(A) R801.2
SIG009106: CN503.1 IC714.1 R735.1 R901.1
SIG009107: Q712.2 Q712.3
SIG009108: Q714.2 Q714.3
SIG009109: C711.2 IC712.3 R723.1 R725.2
SIG009110: IC712.4 R721.1 R727.2
SIG009111: C711.1 R721.2
SIG009112: Q714.6 R723.2
SIG009114: Q713.2(E) R727.1 R729.2
SIG009115: Q713.1(B) R725.1
SIG009116: C715.1 IC714.5 Q713.3(C) R733.1
SIG009117: CN506.2 IC718.1 R911.2
SIG009118: CN504.1 IC716.1 R711.1 R834.1
SIG009119: IC718.6 R836.1
SIG009120: C721.2 IC710.3 R823.1 R825.2
SIG009121: IC718.4 R837.1
SIG009122: C720.1 R820.2
SIG009123: C725.1 IC717.5 Q718.3(C) R833.1
SIG009124: C724.2 IC716.4 R831.2
SIG009125: CN506.1 IC717.1 R835.1 R911.1
SIG009126: Q716.1(B) R824.1
SIG009127: Q718.1(B) R825.1
SIG009128: Q719.6 R823.2
SIG009129: C721.1 R821.2
SIG009130: IC710.4 R821.1 R827.2
SIG009131: C725.2 IC717.4 R832.2
SIG009132: Q716.2(E) R826.1 R828.2
SIG009133: Q717.2 Q717.3
SIG009134: C720.2 IC719.3 R822.1 R824.2
SIG009135: CN504.2 IC718.3 R711.2
SIG009136: Q719.2 Q719.3
SIG009137: C722.2 C723.2 R831.1 R833.2 R838.2
SIG009138: Q718.2(E) R827.1 R829.2
SIG009139: C729.2 CN509.2 R838.1 R839.1
SIG009140: C724.1 IC716.5 Q716.3(C) R830.2
SIG009141: Q717.6 R822.2
SIG009142: IC719.4 R820.1 R826.2
SIG009143: C722.1 C723.1 C729.1 CN509.1 R830.1 R832.1 R839.2
SIG009144: Q816.2 Q816.3
SIG009145: C910.2 IC811.3 R922.1 R924.2
SIG009146: CN911.2 IC815.3 R716.2
SIG009147: C913.1 CN910.1 R930.1 R932.1 R939.2
SIG009148: Q818.2 Q818.3
SIG009149: C914.1 IC813.5 Q815.3(C) R930.2
SIG009150: Q815.2(E) R926.1 R928.2
SIG009151: Q817.2(E) R927.1 R929.2
SIG009152: Q816.6 R922.2
SIG009153: CN913.2 IC815.1 R916.2
SIG009154: IC811.4 R920.1 R926.2
SIG009155: C915.2 IC814.4 R932.2
SIG009156: C911.1 R921.2
SIG009157: Q817.1(B) R925.1
SIG009158: Q815.1(B) R924.1
SIG009159: CN913.1 IC814.1 R916.1 R935.1
SIG009160: IC812.4 R921.1 R927.2
SIG009161: Q818.6 R923.2
SIG009162: CN911.1 IC813.1 R716.1 R934.1
SIG009163: C914.2 IC813.4 R931.2
SIG009164: IC815.4 R937.1
SIG009165: C915.1 IC814.5 Q817.3(C) R933.1
SIG009166: IC815.6 R936.1
SIG009167: C911.2 IC812.3 R923.1 R925.2
SIG009168: C910.1 R920.2
SIG009169: C913.2 CN910.2 R931.1 R933.2 R939.1
SIG009170: IC816.4 R906.1
SIG009171: IC816.6 R706.1
VP_5V_I0_0: L810.2 ; also on sheet 8
VP_5V_I0_1: L811.2 ; also on sheet 8
VP_5V_I0_2: L812.2 ; also on sheet 8
VP_5V_I1_0: L813.2 ; also on sheet 8
VP_5V_I1_1: L814.2 ; also on sheet 8
VP_5V_I1_2: L815.2 ; also on sheet 8
VP_5V_I2_0: L816.2 ; also on sheet 8
VP_5V_I2_1: L817.2 ; also on sheet 8
VP_5V_I2_2: L818.2 ; also on sheet 8
VP_5V_I3_0: L819.2 ; also on sheet 8
VP_5V_I3_1: L820.2 ; also on sheet 8
VP_5V_I3_2: L821.2 ; also on sheet 8
VP_12R0_SYS: J802.2 J806.1 J807.1 J808.1 J809.1 J810.1 J811.1 J812.1 J813.1 ; also on sheet 7
VP_12R0_SYS_I0_0: C821.1(2) C825.2 IC803.1 L802.2 ; also on sheet 8
VP_12R0_SYS_I0_1: L806.2 ; also on sheet 8
VP_12R0_SYS_I1_0: C822.1(2) C826.2 IC804.1 L803.2 ; also on sheet 8
VP_12R0_SYS_I1_1: L807.2 ; also on sheet 8
VP_12R0_SYS_I2_0: C823.1(2) C827.2 IC805.1 L804.2 ; also on sheet 8
VP_12R0_SYS_I2_1: L808.2 ; also on sheet 8
VP_12R0_SYS_I3_0: C824.1(2) C828.2 IC806.1 L805.2 ; also on sheet 8
VP_12R0_SYS_I3_1: L809.2 ; also on sheet 8
VP_DOR: C814.1 IC802.1 IC802.3 J801.1 TP802.1
VP_H: CN6.1 CN6.2 D805.1(A)
VP_L: CN7.1 D800.1(A)
VP_L_0: D801.1(A) ; also on sheet 8
VP_L_1: D802.1(A) ; also on sheet 8
VP_L_2: D803.1(A) ; also on sheet 8
VP_L_3: D804.1(A) ; also on sheet 8

Not connected (* = marked no-connect by the designer): CN7 2; IC710 1 2; IC711 1 2; IC712 1 2; IC719 1 2; IC720 1 2; IC721 1 2; IC722 1 2; IC729 1 2; IC730 1 2; IC731 1 2; IC732 1 2; IC739 1 2; IC740 1 2; IC741 1 2; IC742 1 2; IC749 1 2; IC801 1 7 8 14; IC802 4; IC811 1 2; IC812 1 2; IC817 1 2; IC818 1 2; IC823 1 2; IC824 1 2; IC829 1 2; IC830 1 2

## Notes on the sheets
sheet 1
- ¦CN407 is connected to CN308 of RD210-SCHEMATIC1
- ¦CN408 is connected to CN309 of RD210-SCHEMATIC1
- ¦CN940 is connected to CN310 of RD210-SCHEMATIC1
- <Current Sensing Circuit>
- <Current Sensing Circuit>
- <Current Sensing Circuit>
- BLOCK 3:Hi-Voltage Side
- BLOCK 3:Low-Voltage Side
- BLOCK 3:Coil Current
sheet 2
- ¦CN307 is connected to CN208 of RD210-SCHEMATIC1
- ¦CN308 is connected to CN209 of RD210-SCHEMATIC1
- ¦CN936 is connected to CN210 of RD210-SCHEMATIC1
- <Current Sensing Circuit>
- <Current Sensing Circuit>
- <Current Sensing Circuit>
- BLOCK 2:Hi-Voltage Side
- BLOCK 2:Low-Voltage Side
- BLOCK 2:Coil Current
sheet 3
- ¦CN618 is connected to CN108 of RD210-SCHEMATIC1
- ¦CN208 is connected to CN109 of RD210-SCHEMATIC1
- ¦CN920 is connected to CN110 of RD210-SCHEMATIC1
- <Current Sensing Circuit>
- <Current Sensing Circuit>
- <Current Sensing Circuit>
- BLOCK 1:Hi-Voltage Side
- BLOCK 1:Low-Voltage Side
- BLOCK 1:Coil Current
sheet 4
- ¦CN508 is connected to CN8 of RD210-SCHEMATIC1
- ¦CN509 is connected to CN9 of RD210-SCHEMATIC1
- ¦CN910 is connected to CN10 of RD210-SCHEMATIC1
- <Current Sensing Circuit>
- <Current Sensing Circuit>
- <Current Sensing Circuit>
- BLOCK 0:Hi-Voltage Side
- BLOCK 0:Low-Voltage Side
- BLOCK 0:Coil Current
sheet 5
- ¦CN6 is connected to CN6 of RD210-SCHEMATIC1
- ¦CN7 is connected to CN7 of RD210-SCHEMATIC1
- ¦GND_P0 is connected to GND
